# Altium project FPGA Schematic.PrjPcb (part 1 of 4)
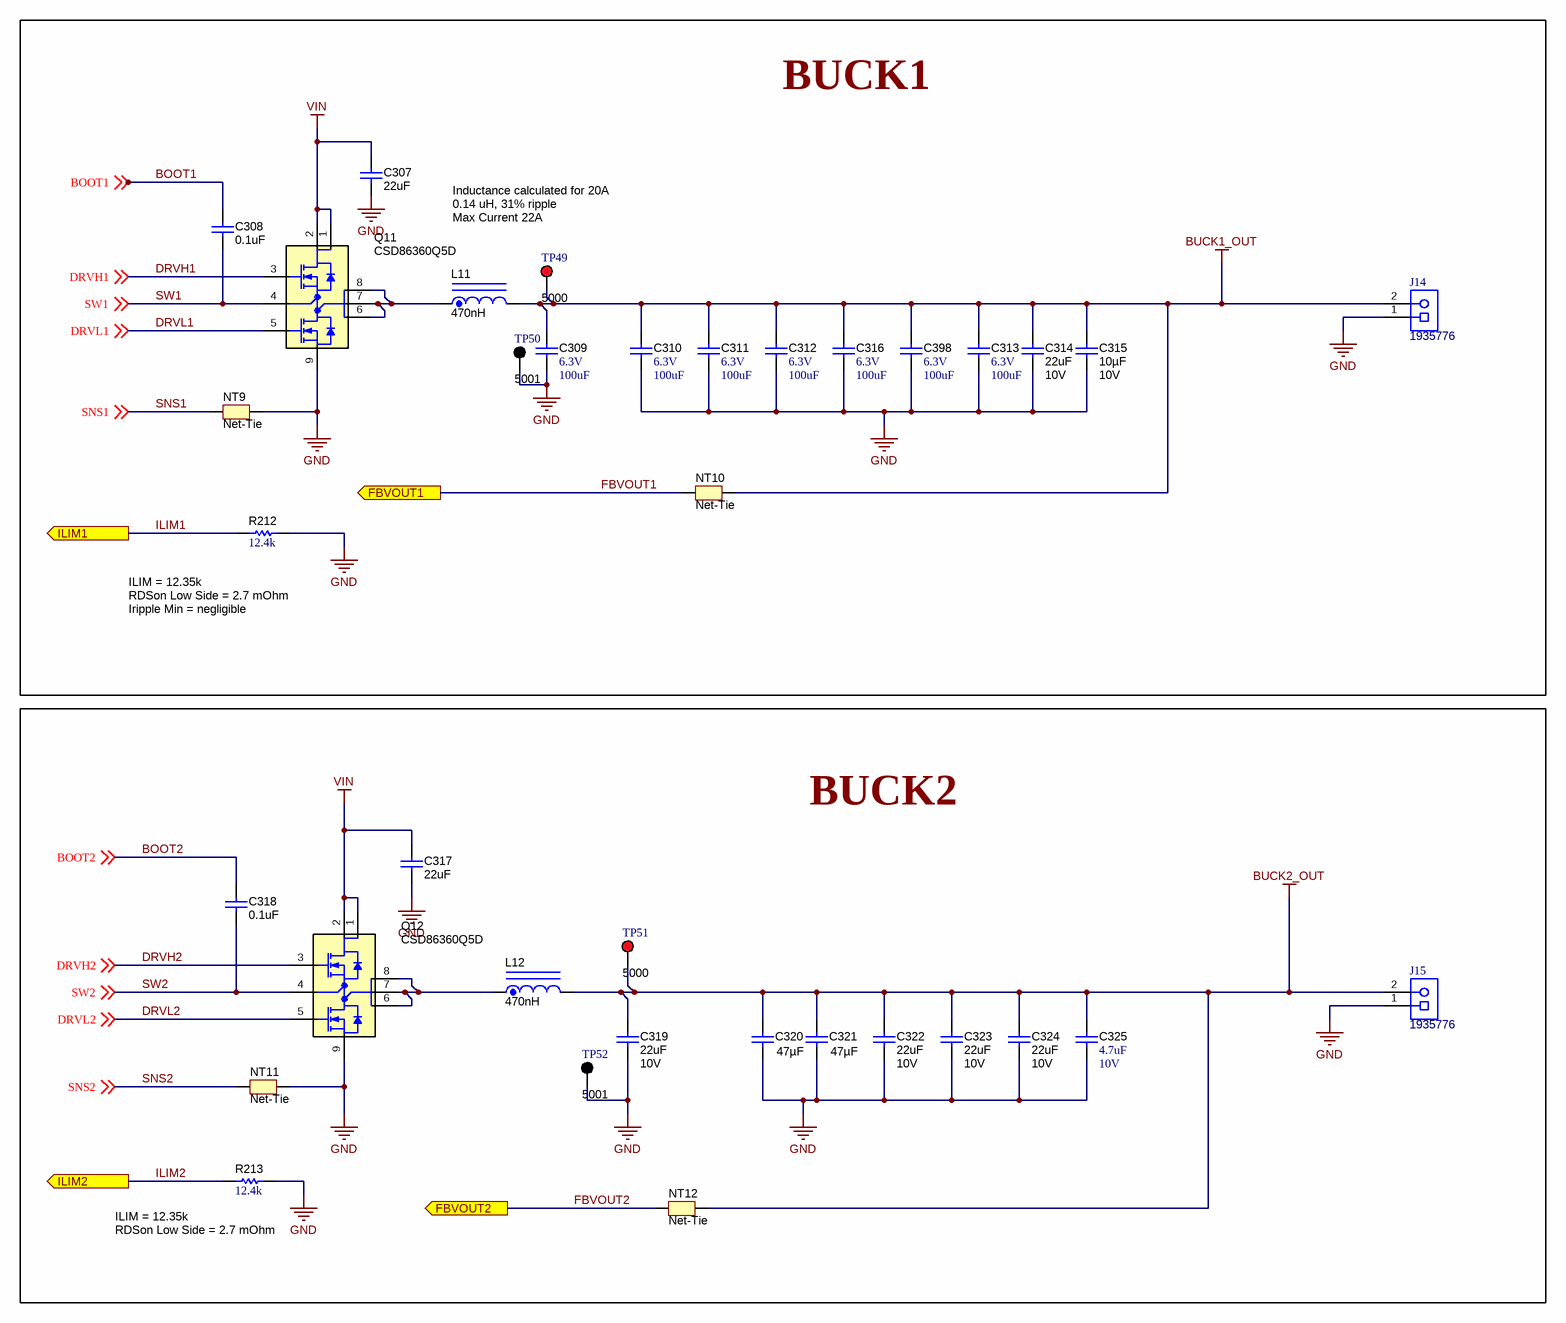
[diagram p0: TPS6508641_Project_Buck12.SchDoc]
TID: TIDA-010241; TechSupport: http://www.ti.com/support; SCH_Rev: E1; PRJ_Title: Flexible FPGA Power; PRJ_Number: TIDA-010241; PRJ_Engineer: Albert Lo; PRJ_Customer: Public Release; PCB_Rev: E1; PCB_Layout: Albert Lo; CopyrightYear: 2021
17 sheets, 877 parts. Net scope: flat (ports and power ports of the same name join across sheets).
Board file: PCB.PcbDoc
Sheets:
  TPS6508641_Project_Buck12.SchDoc
  TPS6508641_Project_Buck6.SchDoc
  TPS6508641_Project_Buck345.SchDoc
  TPS6508641_Project_TPS65086.SchDoc
  TPS6508641_Support_Devices.SchDoc
  TPSM5D1806 IND.SchDoc
  TPSM5D1806 Multi Phase.SchDoc
  EVRHC008_  Filters.SchDoc
  EVRHC008_ CONTROLLER_6X6.SchDoc
  EVRHC008_ Dynamic Load.SchDoc
  EVRHC008_Aux Power.SchDoc
  EVRHC008_HelperCkts and Indicators.SchDoc
  EVRHC008_VOUT_A_Phases 1-2-3.SchDoc
  EVRHC008_VOUT_A_Phases 4-5-6.SchDoc
  EVRHC008_VOUT_B_Phases 1-2.SchDoc
  Hardware.SchDoc
  Block Diagram.SchDoc

## Sheet TPS6508641_Project_Buck12.SchDoc
size 431 x 279 mm; Date: Not shown in title block; ApprovedBy: Not shown in title block; CheckedBy: Not shown in title block; Author: Not shown in title block; CompanyName: Not shown in title block; Engineer: Not shown in title block; Organization: Not shown in title block; Address1: Not shown in title block; Address2: Not shown in title block; Address3: Not shown in title block; Address4: Not shown in title block; DocumentNumber: 11; Revision: Use project parameter SCH_Rev; SheetNumber: 11; SheetTotal: 17; PageSetup: Record=PageOptions¦CenterHorizontal=True¦CenterVertical=True¦PrintScale=0.62¦XCorrection=1.00¦YCorrection=1.00¦PrintKind=0¦BorderSize=5000000¦LeftOffset=0¦BottomOffset=0¦Orientation=2¦PaperLength=1000¦PaperWidth=1000¦Scale=100¦PaperSource=15¦PrintQuality=600¦MediaType=1¦DitherType=10¦PrintScaleMode=1¦PaperKind=Letter

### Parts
C307  ValueDisplayed: 22uF  [0805L]  (hidden comment: GRM21BR61E226ME44L)
C308  ValueDisplayed: 0.1uF  [0201_033L]  (hidden comment: GRM033R61E104KE14J)
C309  VDC_V: 6.3V  ValueDisplayed: 100uF  [0805L]  (hidden comment: GRM21BR60J107M)
C310  VDC_V: 6.3V  ValueDisplayed: 100uF  [0805L]  (hidden comment: GRM21BR60J107M)
C311  VDC_V: 6.3V  ValueDisplayed: 100uF  [0805L]  (hidden comment: GRM21BR60J107M)
C312  VDC_V: 6.3V  ValueDisplayed: 100uF  [0805L]  (hidden comment: GRM21BR60J107M)
C313  VDC_V: 6.3V  ValueDisplayed: 100uF  [0805L]  (hidden comment: GRM21BR60J107M)
C314  ValueDisplayed: 22uF  VDC_V: 10V  [0603S]  (hidden comment: GRM188R61A226ME15D)
C315  ValueDisplayed: 10µF  VDC_V: 10V  [0603S]  (hidden comment: GRM188R61A106KAALD)
C316  VDC_V: 6.3V  ValueDisplayed: 100uF  [0805L]  (hidden comment: GRM21BR60J107M)
C317  ValueDisplayed: 22uF  [0805L]  (hidden comment: GRM21BR61E226ME44L)
C318  ValueDisplayed: 0.1uF  [0201_033L]  (hidden comment: GRM033R61E104KE14J)
C319  ValueDisplayed: 22uF  VDC_V: 10V  [0603S]  (hidden comment: GRM188R61A226ME15D)
C320  ValueDisplayed: 47µF  [0805L]  (hidden comment: GRM21BR61A476ME15L)
C321  ValueDisplayed: 47µF  [0805L]  (hidden comment: GRM21BR61A476ME15L)
C322  ValueDisplayed: 22uF  VDC_V: 10V  [0603S]  (hidden comment: GRM188R61A226ME15D)
C323  ValueDisplayed: 22uF  VDC_V: 10V  [0603S]  (hidden comment: GRM188R61A226ME15D)
C324  ValueDisplayed: 22uF  VDC_V: 10V  [0603S]  (hidden comment: GRM188R61A226ME15D)
C325  ValueDisplayed: 4.7uF  VDC_V: 10V  [0402S]  (hidden comment: GRM155R61A475M)
C398  VDC_V: 6.3V  ValueDisplayed: 100uF  [0805L]  (hidden comment: GRM21BR60J107M)
J14  1935776  [Phoenix_1935776]
J15  1935776  [Phoenix_1935776]
L11  ValueDisplayed: 470nH  [XEL6030_320]  (hidden comment: XEL6030-471MEB)
L12  ValueDisplayed: 470nH  [XEL6030_320]  (hidden comment: XEL6030-471MEB)
NT9  Net-Tie  [Net-Tie6milsWide_20milsLong]  (net tie, no BOM)
NT10  Net-Tie  [Net-Tie6milsWide_20milsLong]  (net tie, no BOM)
NT11  Net-Tie  [Net-Tie6milsWide_20milsLong]  (net tie, no BOM)
NT12  Net-Tie  [Net-Tie6milsWide_20milsLong]  (net tie, no BOM)
Q11  CSD86360Q5D  [DQY0008A]
Q12  CSD86360Q5D  [DQY0008A]
R212  ValueDisplayed: 12.4k  [0402S]  (hidden comment: CRCW040212K4FKED)
R213  ValueDisplayed: 12.4k  [0402S]  (hidden comment: CRCW040212K4FKED)
TP49  5000  [Keystone5000]
TP50  5001  [Keystone5001]
TP51  5000  [Keystone5000]
TP52  5001  [Keystone5001]

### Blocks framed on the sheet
BUCK1: C307-C316 C398 J14 L11 NT9 NT10 Q11 R212 TP49 TP50
BUCK2: C317-C325 J15 L12 NT11 NT12 Q12 R213 TP51 TP52

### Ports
FBVOUT1 (out), FBVOUT2 (out), ILIM1 (out), ILIM2 (out)

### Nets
BUCK1_OUT: C309.1 C310.1 C311.1 C312.1 C313.1 C314.2 C315.2 C316.1 C398.1 J14.2 L11.2 NT10.2 TP49.1
BUCK2_OUT: C319.2 C320.1 C321.1 C322.2 C323.2 C324.2 C325.1 J15.2 L12.2 NT12.2 TP51.1
GND: C307.2 C309.2 C310.2 C311.2 C312.2 C313.2 C314.1 C315.1 C316.2 C317.2 C319.1 C320.2 C321.2 C322.1 C323.1 C324.1 C325.2 C398.2 J14.1 J15.1 NT9.2 NT11.2 Q11.9(PGND) Q12.9(PGND) R212.2 R213.2 TP50.1 TP52.1
VIN: C307.1 C317.1 Q11.1(VIN) Q11.2(VIN) Q12.1(VIN) Q12.2(VIN)
BOOT1: C308.1 ; off-sheet BOOT1
BOOT2: C318.1 ; off-sheet BOOT2
DRVH1: Q11.3(TG) ; off-sheet DRVH1
DRVH2: Q12.3(TG) ; off-sheet DRVH2
DRVL1: Q11.5(BG) ; off-sheet DRVL1
DRVL2: Q12.5(BG) ; off-sheet DRVL2
FBVOUT1: NT10.1 ; port FBVOUT1
FBVOUT2: NT12.1 ; port FBVOUT2
ILIM1: R212.1 ; port ILIM1
ILIM2: R213.1 ; port ILIM2
SNS1: NT9.1 ; off-sheet SNS1
SNS2: NT11.1 ; off-sheet SNS2
SW1: C308.2 Q11.4(TGR) ; off-sheet SW1
SW2: C318.2 Q12.4(TGR) ; off-sheet SW2
NetL11_1: L11.1 Q11.6(VSW) Q11.7(VSW) Q11.8(VSW)
NetL12_1: L12.1 Q12.6(VSW) Q12.7(VSW) Q12.8(VSW)

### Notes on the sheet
- Inductance calculated for 20A
  0.14 uH, 31% ripple
  Max Current 22A
- (near R212) ILIM = 12.35k
  RDSon Low Side = 2.7 mOhm
  Iripple Min = negligible
- (near R213) ILIM = 12.35k
  RDSon Low Side = 2.7 mOhm

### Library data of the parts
C307 C317 = CMP-0008305-2: CAP, CERM, 22 uF, 25 V, +/- 20%, X5R, 0805; Manufacturer: MuRata; TaMin_C: -55°C; Polarized: N; SizeAreaWB_mm2: 6.75; Value1: Unknown; U/M: EA; Value: 22uF; TaMax_C: 85°C; SizeZ_mm: 1.45; SizeX_mm: 2; SizeY_mm: 1.25; Cap_Case: 0805; Value2: 25V; SizeArea_mm2: 2.5; Cap_F: 22µF; AEC Category: Q200
C308 C318 = CMP-0009719-2: CAP, CERM, 0.1 uF, 25 V, +/- 10%, X5R, 0201; Manufacturer: MuRata; TaMin_C: -55°C; Polarized: N; SizeAreaWB_mm2: 2.08; Value1: Unknown; U/M: EA; Value: 0.1uF; TaMax_C: 85°C; SizeZ_mm: 0.33; SizeX_mm: 0.6; SizeY_mm: 0.3; Cap_Case: 0201; Value2: 25V; SizeArea_mm2: 0.18; Cap_F: 100nF; AEC Category: Q200
C309-C313 C316 C398 = CMP-0008280-2: CAP, CERM, 100 uF, 6.3 V, +/- 20%, X5R, 0805; Manufacturer: MuRata; TaMin_C: -55°C; Polarized: N; SizeAreaWB_mm2: 6.75; Value1: Unknown; U/M: EA; Value: 100uF; TaMax_C: 85°C; SizeZ_mm: 1.45; SizeX_mm: 2; SizeY_mm: 1.25; Cap_Case: 0805; SizeArea_mm2: 2.5; Cap_F: 100µF; AEC Category: Q200
C314 C319 C322-C324 = CMP-0007324-5: CAP, CERM, 22 uF, 10 V, +/- 20%, X5R, 0603; Manufacturer: MuRata; Polarized: N; Value: 22uF; U/M: EA; Cap_F: 22µF; Value1: Unknown; TaMin_C: -55°C; TaMax_C: 85°C; Cap_Case: 0603; SizeArea_mm2: 1.28; SizeAreaWB_mm2: 4.68; SizeX_mm: 1.6; SizeY_mm: 0.8; SizeZ_mm: 1; AEC Category: Q200
C315 = CMP-0086193-1: CAP, CERM, 10 µF, 10 V,+/- 10%, X5R, 0603; Manufacturer: MuRata; Polarized: N; Value: 10uF; U/M: EA; TaMin_C: -55°C; TaMax_C: 85°C; Cap_Case: 0603; SizeArea_mm2: 1.28; SizeAreaWB_mm2: 4.68; SizeX_mm: 1.6; SizeY_mm: 0.8; SizeZ_mm: 1; AEC Category: Q200
C320 C321 = CMP-0078699-1: CAP, CERM, 47 µF, 10 V,+/- 20%, X5R, 0805; Manufacturer: MuRata; TaMin_C: -55°C; Polarized: N; Green_Lifecycle: Active; SizeAreaWB_mm2: 6.75; Green_REACh: Passed; U/M: EA; Value: 47uF; TaMax_C: 85°C; SizeZ_mm: 1.45; SizeX_mm: 2; SizeY_mm: 1.25; Cap_Case: 0805; Value2: 10V; SizeArea_mm2: 2.5; AEC Category: Q200
C325 = CMP-0006581-2: CAP, CERM, 4.7 uF, 10 V, +/- 20%, X5R, 0402; Manufacturer: MuRata; Polarized: N; Value: 4.7uF; U/M: EA; Cap_F: 4.7µF; Value1: Unknown; TaMin_C: -55°C; TaMax_C: 85°C; Cap_Case: 0402; SizeArea_mm2: 0.5; SizeAreaWB_mm2: 3; SizeX_mm: 1; SizeZ_mm: 0.6; AEC Category: Q200
J14 J15 = CMP-0055506-1: Terminal Block, 2x1, 5mm, Green, TH; Manufacturer: Phoenix Contact; Pitch_mm: 5; Gender: Female; Row_Count: 1; CNHeader: FALSE; Green_Lifecycle: Not Set; Green_REACh: Incomplete; CT: TRUE
L11 = CMP-0061103-3: Inductor, Shielded, Composite, 470 nH, 22.3 A, 0.00331 ohm, AEC-Q200 Grade 1, SMD; Manufacturer: Coilcraft; Irms: 22.3A @ 40C rise; Value2: 22.3A; AEC Category: Q200; DCR_ohm: 3.31m; SizeX_mm: 6.36; SizeArea_mm2: 41.7216; SizeAreaWB_mm2: 71.5616; AEC Grade: 1; SizeY_mm: 6.56; Isat: 24A @ 30% inductance drop; SizeZ_mm: 3.2; Value: 470nH; AEC Qualified: Y
L12 = CMP-0061103-3: Inductor, Shielded, Composite, 470 nH, 22.3 A, 0.00331 ohm, AEC-Q200 Grade 1, SMD; Manufacturer: Coilcraft; Isat: 24A @ 30% inductance drop; Irms: 22.3A @ 40C rise; SizeAreaWB_mm2: 71.5616; DCR_ohm: 3.31m; Value: 470nH; Imax_A: 22.3A; SizeZ_mm: 3.2; SizeX_mm: 6.36; SizeY_mm: 6.56; SizeArea_mm2: 41.7216; AEC Qualified: Y; AEC Grade: 1; AEC Category: Q200
NT9-NT12 = CMP-0078142-4: Single point connection between nets.
Q11 Q12 = CMP-0000278-2: MOSFET, 2-CH, N-CH, 25 V, 50 A, DQY0008A (LSON-CLIP-8); Alternate Manufacturer: None; Manufacturer: Texas Instruments; SizeZ_mm: 1.6; ChType: N; Value2: 9.7 nC; Value1: 0.004; VdsMax_V: 25V; SizeX_mm: 6; SizeY_mm: 5; Vgs_V: 10V; Value: 25V; Rdson45_ohm: 4.5m; SizeArea_mm2: 30; AEC Category: Q101; IdsMax_A: 50A; SizeAreaWB_mm2: 56; QgTyp_nC: 9.7; ChMode: Enhancement
R212 R213 = CMP-0025992-3: RES, 12.4 k, 1%, 0.063 W, AEC-Q200 Grade 0, 0402; Manufacturer: Vishay-Dale; Power_W: 63mW; TempCo: 100 ppm/C; Value_Code: 12k4; Value: 12.4k; EIA_Code: E96; SizeX_mm: 1; SizeY_mm: 0.5; SizeZ_mm: 0.6; Value2: 0.063W; AEC Qualified: Y; VDC_V: 50V; AEC Category: Q200; AEC Grade: 0
TP49 TP51 = CMP-0055137-1: Test Point, Miniature, Red, TH; Manufacturer: Keystone; ContactFinish: Silver; CNHeader: FALSE; Green_Lifecycle: Active; Green_REACh: Passed; CT: TRUE
TP50 TP52 = CMP-0055138-1: Test Point, Miniature, Black, TH; Manufacturer: Keystone; ContactFinish: Silver; CNHeader: FALSE; Green_Lifecycle: Active; Green_REACh: Passed; CT: TRUE

## Sheet TPS6508641_Project_Buck6.SchDoc
size 431 x 279 mm; Date: Not shown in title block; ApprovedBy: Not shown in title block; CheckedBy: Not shown in title block; Author: Not shown in title block; CompanyName: Not shown in title block; Engineer: Not shown in title block; Organization: Not shown in title block; Address1: Not shown in title block; Address2: Not shown in title block; Address3: Not shown in title block; Address4: Not shown in title block; DocumentNumber: 12; Revision: Use project parameter SCH_Rev; SheetNumber: 12; SheetTotal: 17; PageSetup: Record=PageOptions¦CenterHorizontal=True¦CenterVertical=True¦PrintScale=1.00¦XCorrection=1.00¦YCorrection=1.00¦PrintKind=0¦BorderSize=5000000¦LeftOffset=0¦BottomOffset=0¦Orientation=2¦PaperLength=1000¦PaperWidth=1000¦Scale=100¦PaperSource=15¦PrintQuality=600¦MediaType=1¦DitherType=10¦PaperKind=Letter¦PrintScaleMode=1
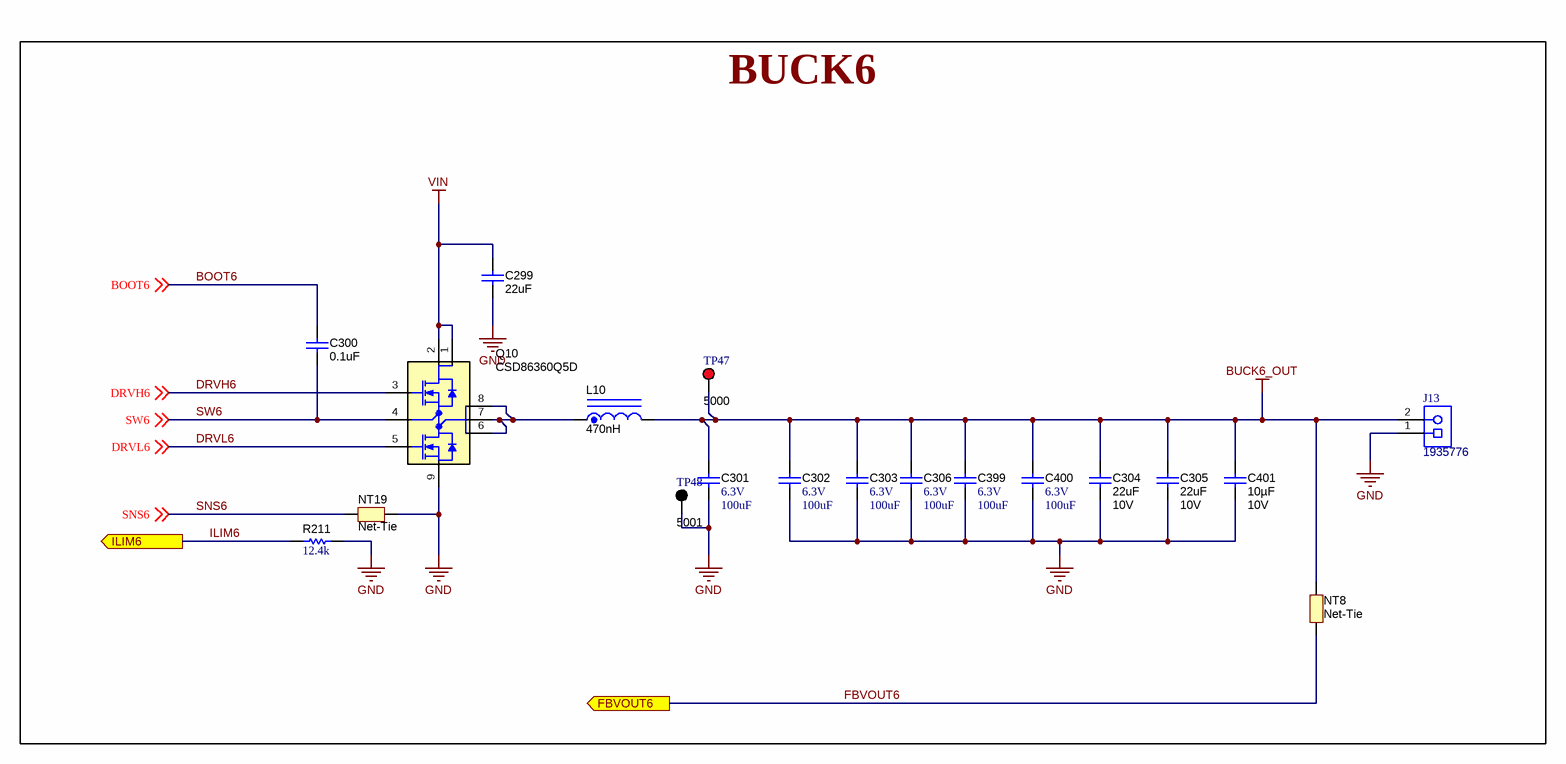
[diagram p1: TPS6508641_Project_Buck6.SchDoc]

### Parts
C299  ValueDisplayed: 22uF  [0805L]  (hidden comment: GRM21BR61E226ME44L)
C300  ValueDisplayed: 0.1uF  [0201_033L]  (hidden comment: GRM033R61E104KE14J)
C301  VDC_V: 6.3V  ValueDisplayed: 100uF  [0805L]  (hidden comment: GRM21BR60J107M)
C302  VDC_V: 6.3V  ValueDisplayed: 100uF  [0805L]  (hidden comment: GRM21BR60J107M)
C303  VDC_V: 6.3V  ValueDisplayed: 100uF  [0805L]  (hidden comment: GRM21BR60J107M)
C304  ValueDisplayed: 22uF  VDC_V: 10V  [0603S]  (hidden comment: GRM188R61A226ME15D)
C305  ValueDisplayed: 22uF  VDC_V: 10V  [0603S]  (hidden comment: GRM188R61A226ME15D)
C306  VDC_V: 6.3V  ValueDisplayed: 100uF  [0805L]  (hidden comment: GRM21BR60J107M)
C399  VDC_V: 6.3V  ValueDisplayed: 100uF  [0805L]  (hidden comment: GRM21BR60J107M)
C400  VDC_V: 6.3V  ValueDisplayed: 100uF  [0805L]  (hidden comment: GRM21BR60J107M)
C401  ValueDisplayed: 10µF  VDC_V: 10V  [0603S]  (hidden comment: GRM188R61A106KAALD)
J13  1935776  [Phoenix_1935776]
L10  ValueDisplayed: 470nH  [XEL6030_320]  (hidden comment: XEL6030-471MEB)
NT8  Net-Tie  [Net-Tie6milsWide_20milsLong]  (net tie, no BOM)
NT19  Net-Tie  [Net-Tie6milsWide_20milsLong]  (net tie, no BOM)
Q10  CSD86360Q5D  [DQY0008A]
R211  ValueDisplayed: 12.4k  [0402S]  (hidden comment: CRCW040212K4FKED)
TP47  5000  [Keystone5000]
TP48  5001  [Keystone5001]

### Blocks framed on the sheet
BUCK6: C299-C306 C399-C401 J13 L10 NT8 NT19 Q10 R211 TP47 TP48

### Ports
FBVOUT6 (out), ILIM6 (out)

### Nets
BUCK6_OUT: C301.1 C302.1 C303.1 C304.2 C305.2 C306.1 C399.1 C400.1 C401.2 J13.2 L10.2 NT8.2 TP47.1
GND: C299.2 C301.2 C302.2 C303.2 C304.1 C305.1 C306.2 C399.2 C400.2 C401.1 J13.1 NT19.2 Q10.9(PGND) R211.2 TP48.1
VIN: C299.1 Q10.1(VIN) Q10.2(VIN)
BOOT6: C300.1 ; off-sheet BOOT6
DRVH6: Q10.3(TG) ; off-sheet DRVH6
DRVL6: Q10.5(BG) ; off-sheet DRVL6
FBVOUT6: NT8.1 ; port FBVOUT6
ILIM6: R211.1 ; port ILIM6
SNS6: NT19.1 ; off-sheet SNS6
SW6: C300.2 Q10.4(TGR) ; off-sheet SW6
NetL10_1: L10.1 Q10.6(VSW) Q10.7(VSW) Q10.8(VSW)

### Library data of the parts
C299 = CMP-0008305-2: as C307 on sheet TPS6508641_Project_Buck12
C300 = CMP-0009719-2: as C308 on sheet TPS6508641_Project_Buck12
C301-C303 C306 C399 C400 = CMP-0008280-2: as C309 on sheet TPS6508641_Project_Buck12
C304 C305 = CMP-0007324-5: as C314 on sheet TPS6508641_Project_Buck12
C401 = CMP-0086193-1: as C315 on sheet TPS6508641_Project_Buck12
J13 = CMP-0055506-1: as J14 on sheet TPS6508641_Project_Buck12
L10 = CMP-0061103-3: as L12 on sheet TPS6508641_Project_Buck12
NT8 NT19 = CMP-0078142-4: Single point connection between nets.
Q10 = CMP-0000278-2: as Q11 on sheet TPS6508641_Project_Buck12
R211 = CMP-0025992-3: as R212 on sheet TPS6508641_Project_Buck12
TP47 = CMP-0055137-1: as TP49 on sheet TPS6508641_Project_Buck12
TP48 = CMP-0055138-1: as TP50 on sheet TPS6508641_Project_Buck12

## Sheet TPS6508641_Project_Buck345.SchDoc
size 431 x 279 mm; Date: Not shown in title block; ApprovedBy: Not shown in title block; CheckedBy: Not shown in title block; Author: Not shown in title block; CompanyName: Not shown in title block; Engineer: Not shown in title block; Organization: Not shown in title block; Address1: Not shown in title block; Address2: Not shown in title block; Address3: Not shown in title block; Address4: Not shown in title block; DocumentNumber: 13; Revision: Use project parameter SCH_Rev; SheetNumber: 13; SheetTotal: 17; PageSetup: Record=PageOptions¦CenterHorizontal=True¦CenterVertical=True¦PrintScale=1.00¦XCorrection=1.00¦YCorrection=1.00¦PrintKind=0¦BorderSize=5000000¦LeftOffset=0¦BottomOffset=0¦Orientation=2¦PaperLength=1000¦PaperWidth=1000¦Scale=100¦PaperSource=15¦PrintQuality=600¦MediaType=1¦DitherType=10¦PaperKind=Letter¦PrintScaleMode=1
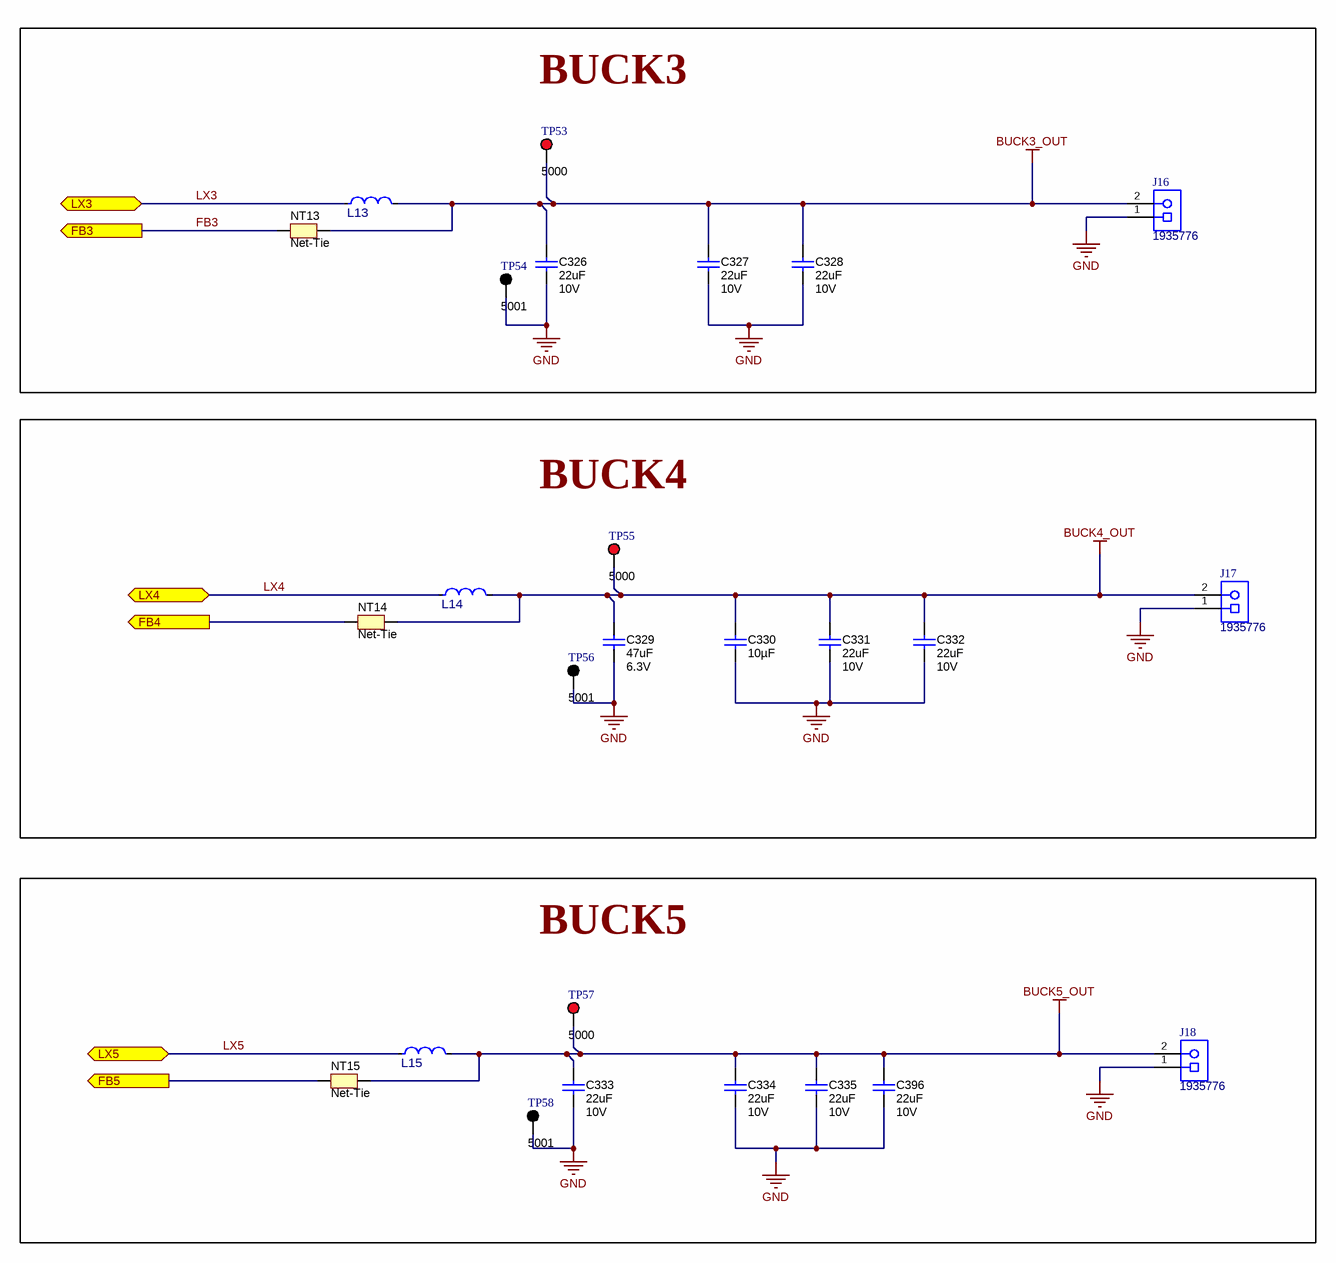
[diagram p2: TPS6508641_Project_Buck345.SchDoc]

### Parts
C326  ValueDisplayed: 22uF  VDC_V: 10V  [0603S]  (hidden comment: GRM188R61A226ME15D)
C327  ValueDisplayed: 22uF  VDC_V: 10V  [0603S]  (hidden comment: GRM188R61A226ME15D)
C328  ValueDisplayed: 22uF  VDC_V: 10V  [0603S]  (hidden comment: GRM188R61A226ME15D)
C329  ValueDisplayed: 47uF  VDC_V: 6.3V  [0603S]  (hidden comment: GRM188R60J476ME15D)
C330  ValueDisplayed: 10µF  [0603S]  (hidden comment: GRM188R61A106KAALD)
C331  ValueDisplayed: 22uF  VDC_V: 10V  [0603S]  (hidden comment: GRM188R61A226ME15D)
C332  ValueDisplayed: 22uF  VDC_V: 10V  [0603S]  (hidden comment: GRM188R61A226ME15D)
C333  ValueDisplayed: 22uF  VDC_V: 10V  [0603S]  (hidden comment: GRM188R61A226ME15D)
C334  ValueDisplayed: 22uF  VDC_V: 10V  [0603S]  (hidden comment: GRM188R61A226ME15D)
C335  ValueDisplayed: 22uF  VDC_V: 10V  [0603S]  (hidden comment: GRM188R61A226ME15D)
C396  ValueDisplayed: 22uF  VDC_V: 10V  [0603S]  (hidden comment: GRM188R61A226ME15D)
J16  1935776  [Phoenix_1935776]
J17  1935776  [Phoenix_1935776]
J18  1935776  [Phoenix_1935776]
L13  XEL3530-501MEC  [FP-XEL3530-501MEC_SMT_IND_3MM2_3MM5-MFG]  (value not drawn)
L14  XEL3530-501MEC  [FP-XEL3530-501MEC_SMT_IND_3MM2_3MM5-MFG]  (value not drawn)
L15  XEL3530-501MEC  [FP-XEL3530-501MEC_SMT_IND_3MM2_3MM5-MFG]  (value not drawn)
NT13  Net-Tie  [Net-Tie6milsWide_20milsLong]  (net tie, no BOM)
NT14  Net-Tie  [Net-Tie6milsWide_20milsLong]  (net tie, no BOM)
NT15  Net-Tie  [Net-Tie6milsWide_20milsLong]  (net tie, no BOM)
TP53  5000  [Keystone5000]
TP54  5001  [Keystone5001]
TP55  5000  [Keystone5000]
TP56  5001  [Keystone5001]
TP57  5000  [Keystone5000]
TP58  5001  [Keystone5001]

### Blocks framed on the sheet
BUCK3: C326-C328 J16 L13 NT13 TP53 TP54
BUCK4: C329-C332 J17 L14 NT14 TP55 TP56
BUCK5: C333-C335 C396 J18 L15 NT15 TP57 TP58

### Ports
FB3 (out), FB4 (out), FB5 (out), LX3 (bidir), LX4 (bidir), LX5 (bidir)

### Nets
BUCK3_OUT: C326.2 C327.2 C328.2 J16.2 L13.2 NT13.2 TP53.1
BUCK4_OUT: C329.1 C330.1 C331.2 C332.2 J17.2 L14.2 NT14.2 TP55.1
BUCK5_OUT: C333.2 C334.2 C335.2 C396.2 J18.2 L15.2 NT15.2 TP57.1
GND: C326.1 C327.1 C328.1 C329.2 C330.2 C331.1 C332.1 C333.1 C334.1 C335.1 C396.1 J16.1 J17.1 J18.1 TP54.1 TP56.1 TP58.1
FB3: NT13.1 ; port FB3
FB4: NT14.1 ; port FB4
FB5: NT15.1 ; port FB5
LX3: L13.1 ; port LX3
LX4: L14.1 ; port LX4
LX5: L15.1 ; port LX5

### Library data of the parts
C326-C328 C331-C335 C396 = CMP-0007324-5: as C314 on sheet TPS6508641_Project_Buck12
C329 = CMP-0007313-5: CAP, CERM, 47 uF, 6.3 V, +/- 20%, X5R, 0603; Manufacturer: MuRata; Polarized: N; Value: 47uF; U/M: EA; Cap_F: 47µF; Value1: Unknown; TaMin_C: -55°C; TaMax_C: 85°C; Cap_Case: 0603; SizeArea_mm2: 1.28; SizeAreaWB_mm2: 4.68; SizeX_mm: 1.6; SizeY_mm: 0.8; SizeZ_mm: 1; AEC Category: Q200
C330 = CMP-0086193-1: CAP, CERM, 10 µF, 10 V,+/- 10%, X5R, 0603; Manufacturer: MuRata; SizeArea_mm2: 1.28; SizeY_mm: 0.8; TaMax_C: 85°C; TaMin_C: -55°C; VDC_V: 10V; Polarized: N; SizeAreaWB_mm2: 4.68; SizeZ_mm: 1; SizeX_mm: 1.6; AEC Category: Q200; Cap_Case: 0603; U/M: EA; Value: 10uF
J16-J18 = CMP-0055506-1: as J14 on sheet TPS6508641_Project_Buck12
L13-L15 = CMP-0087112-1: Shielded Power Inductors; Manufacturer: Coilcraft; Isat: 3.7A; Irms: 8.5A; DCR_ohm: 8.35m; Material: Composite; SizeZ_mm: 3mm; Ind_H: 500nH; AEC Qualified: Yes; AEC Grade: Grade 1
NT13-NT15 = CMP-0078142-4: Single point connection between nets.
TP53 TP55 TP57 = CMP-0055137-1: as TP49 on sheet TPS6508641_Project_Buck12
TP54 TP56 TP58 = CMP-0055138-1: as TP50 on sheet TPS6508641_Project_Buck12

## Sheet TPS6508641_Project_TPS65086.SchDoc
size 431 x 279 mm; Date: Not shown in title block; ApprovedBy: Not shown in title block; CheckedBy: Not shown in title block; Author: Not shown in title block; CompanyName: Not shown in title block; Engineer: Not shown in title block; Organization: Not shown in title block; Address1: Not shown in title block; Address2: Not shown in title block; Address3: Not shown in title block; Address4: Not shown in title block; DocumentNumber: 10; Revision: Use project parameter SCH_Rev; SheetNumber: 10; SheetTotal: 17; PageSetup: Record=PageOptions¦CenterHorizontal=True¦CenterVertical=True¦PrintScale=1.00¦XCorrection=1.00¦YCorrection=1.00¦PrintKind=0¦BorderSize=5000000¦LeftOffset=0¦BottomOffset=0¦Orientation=2¦PaperLength=1000¦PaperWidth=1000¦Scale=100¦PaperSource=15¦PrintQuality=600¦MediaType=1¦DitherType=10¦PaperKind=Letter¦PrintScaleMode=1
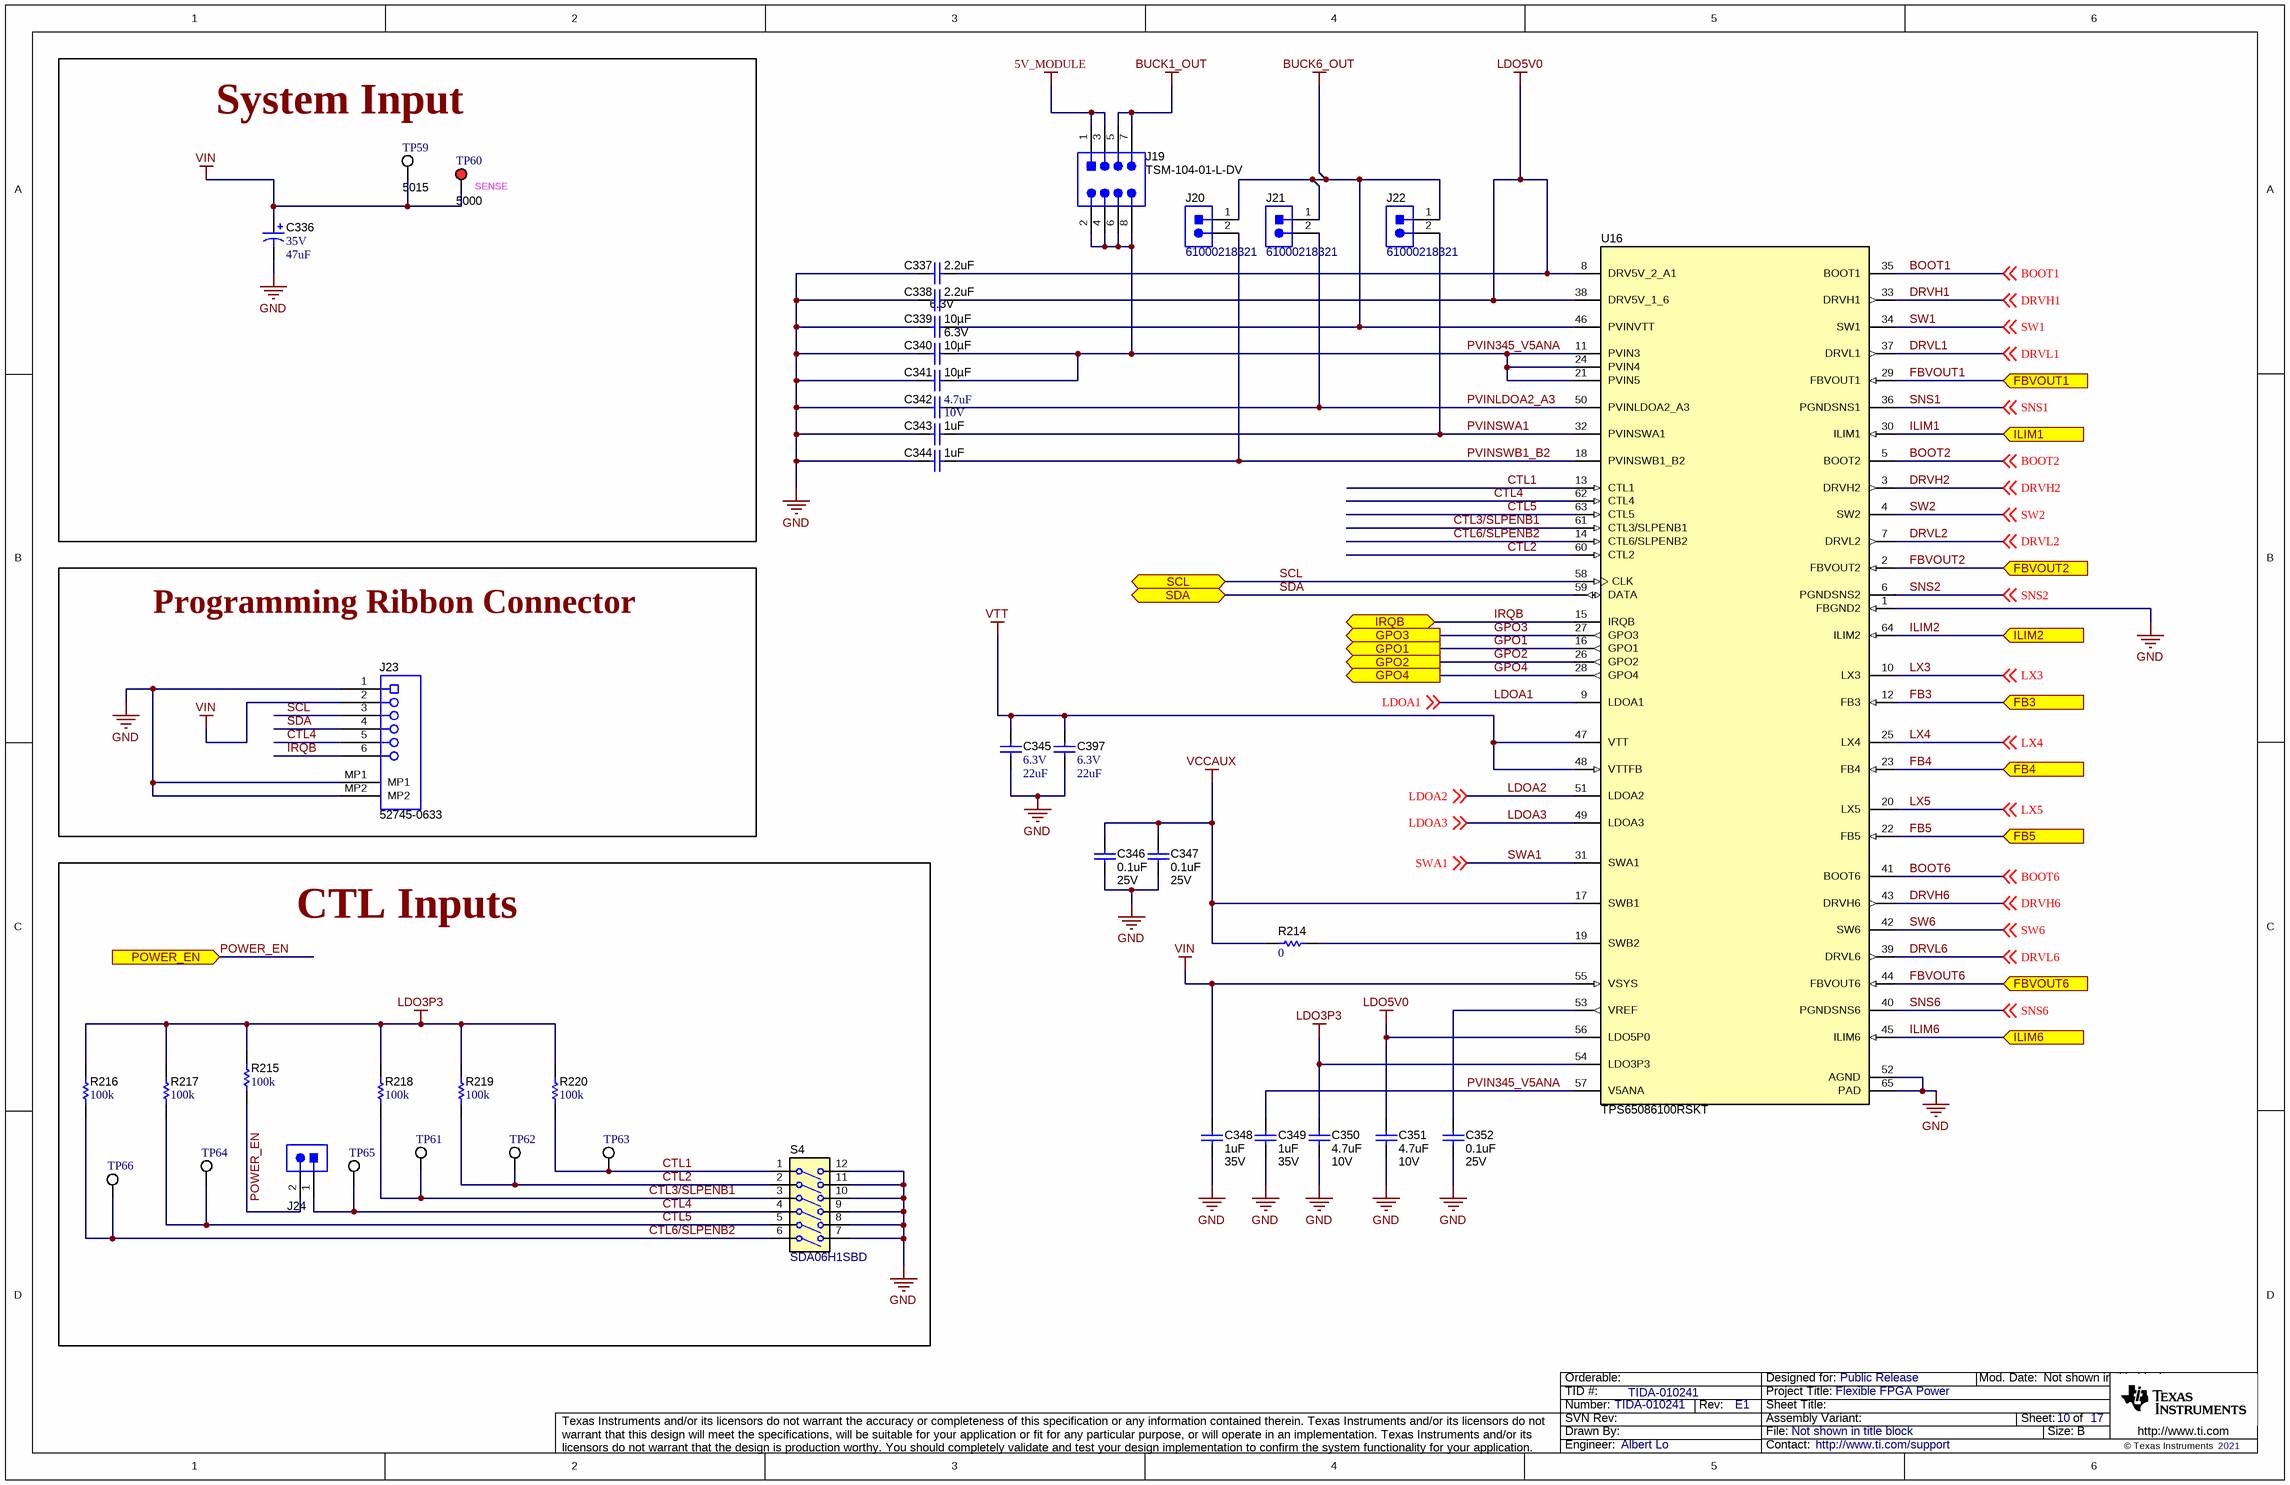
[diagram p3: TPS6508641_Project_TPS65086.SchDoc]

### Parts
C336  VDC_V: 35V  ValueDisplayed: 47uF  [7343-43]  (hidden comment: TAJE476M035RNJ)
C337  ValueDisplayed: 2.2uF  VDC_V: 6.3V  [0402S]  (hidden comment: GRM155R60J225KE95D)
C338  ValueDisplayed: 2.2uF  VDC_V: 6.3V  [0402S]  (hidden comment: GRM155R60J225KE95D)
C339  ValueDisplayed: 10µF  [0603S]  (hidden comment: GRM188R61A106KAALD)
C340  ValueDisplayed: 10µF  [0603S]  (hidden comment: GRM188R61A106KAALD)
C341  ValueDisplayed: 10µF  [0603S]  (hidden comment: GRM188R61A106KAALD)
C342  VDC_V: 10V  ValueDisplayed: 4.7uF  [0402_065]  (hidden comment: C1005X5R1A475K050BC)
C343  ValueDisplayed: 1uF  [0201L]  (hidden comment: GRM033R61A105ME15D)
C344  ValueDisplayed: 1uF  [0201L]  (hidden comment: GRM033R61A105ME15D)
C345  VDC_V: 6.3V  ValueDisplayed: 22uF  [0402S]  (hidden comment: GRM155R60J226ME11D)
C346  ValueDisplayed: 0.1uF  VDC_V: 25V  [0201_033L]  (hidden comment: GRM033R61E104KE14J)
C347  ValueDisplayed: 0.1uF  VDC_V: 25V  [0201_033L]  (hidden comment: GRM033R61E104KE14J)
C348  ValueDisplayed: 1uF  VDC_V: 35V  [0402S]  (hidden comment: GRM155R6YA105ME11D)
C349  ValueDisplayed: 1uF  VDC_V: 35V  [0402S]  (hidden comment: GRM155R6YA105ME11D)
C350  ValueDisplayed: 4.7uF  VDC_V: 10V  [0402S]  (hidden comment: C1005X5R1A475M050BC)
C351  ValueDisplayed: 4.7uF  VDC_V: 10V  [0402S]  (hidden comment: C1005X5R1A475M050BC)
C352  ValueDisplayed: 0.1uF  VDC_V: 25V  [0201_033L]  (hidden comment: GRM033R61E104KE14J)
C397  VDC_V: 6.3V  ValueDisplayed: 22uF  [0402S]  (hidden comment: GRM155R60J226ME11D)
J19  TSM-104-01-L-DV  [Samtec_TSM-104-01-x-DV]
J20  61000218321  [Wurth_61000218321]
J21  61000218321  [Wurth_61000218321]
J22  61000218321  [Wurth_61000218321]
J23  52745-0633  [Molex_52745-0633]
J24  TSW-102-07-G-S  [TSW-102-07-G-S]  (value not drawn)
R214  ValueDisplayed: 0  [0402S]  (hidden comment: CRCW04020000Z0ED)
R215  ValueDisplayed: 100k  [0402S]  (hidden comment: CRCW0402100KJNED)
R216  ValueDisplayed: 100k  [0402S]  (hidden comment: CRCW0402100KJNED)
R217  ValueDisplayed: 100k  [0402S]  (hidden comment: CRCW0402100KJNED)
R218  ValueDisplayed: 100k  [0402S]  (hidden comment: CRCW0402100KJNED)
R219  ValueDisplayed: 100k  [0402S]  (hidden comment: CRCW0402100KJNED)
R220  ValueDisplayed: 100k  [0402S]  (hidden comment: CRCW0402100KJNED)
S4  SDA06H1SBD  [SW_SDA06H1SBD]
TP59  5015  [Testpoint_Keystone_Miniature]
TP60  5000  [Keystone5000]
TP61  5015  [Testpoint_Keystone_Miniature]  (value not drawn)
TP62  5015  [Testpoint_Keystone_Miniature]  (value not drawn)
TP63  5015  [Testpoint_Keystone_Miniature]  (value not drawn)
TP64  5015  [Testpoint_Keystone_Miniature]  (value not drawn)
TP65  5015  [Testpoint_Keystone_Miniature]  (value not drawn)
TP66  5015  [Testpoint_Keystone_Miniature]  (value not drawn)
U16  TPS65086100RSKT  [RSK0064C]

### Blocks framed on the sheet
System Input: C336 TP59 TP60
Programming Ribbon Connector: J23
CTL Inputs: J24 R215-R220 S4 TP61-TP66

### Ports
FB3 (in), FB4 (in), FB5 (in), FBVOUT1 (in), FBVOUT2 (in), FBVOUT6 (in), GPO1 (out), GPO2 (out), GPO3 (out), GPO4 (out), ILIM1 (in), ILIM2 (in), ILIM6 (in), IRQB (bidir), POWER_EN (in), SCL (bidir), SDA (bidir)

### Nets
5V_MODULE: J19.1 J19.3
BUCK1_OUT: J19.5 J19.7
BUCK6_OUT: C339.1 J20.1 J21.1 J22.1 U16.46(PVINVTT)
GND: C336.2(-) C337.2 C338.2 C339.2 C340.2 C341.2 C342.2 C343.2 C344.2 C345.2 C346.2 C347.2 C348.2 C349.2 C350.2 C351.2 C352.2 C397.2 J23.1 J23.MP1 J23.MP2 S4.7(6A) S4.8(5A) S4.9(4A) S4.10(3A) S4.11(2A) S4.12(1A) U16.1(FBGND2) U16.52(AGND) U16.65(PAD)
LDO3P3: C350.1 R215.2 R216.2 R217.2 R218.2 R219.2 R220.2 U16.54(LDO3P3)
LDO5V0: C337.1 C338.1 C351.1 U16.8(DRV5V_2_A1) U16.38(DRV5V_1_6) U16.56(LDO5P0)
VCCAUX: C346.1 C347.1 R214.2 U16.17(SWB1)
VIN: C336.1(+) C348.1 J23.2 TP59.1 TP60.1 U16.55(VSYS)
VTT: C345.1 C397.1 U16.47(VTT) U16.48(VTTFB)
BOOT1: U16.35(BOOT1) ; off-sheet BOOT1
BOOT2: U16.5(BOOT2) ; off-sheet BOOT2
BOOT6: U16.41(BOOT6) ; off-sheet BOOT6
CTL1: R220.1 S4.1 TP63.1 U16.13(CTL1)
CTL2: R219.1 S4.2 TP62.1 U16.60(CTL2)
CTL3/SLPENB1: R218.1 S4.3 TP61.1 U16.61(CTL3/SLPENB1)
CTL4: J23.5 J24.1 S4.4 TP65.1 U16.62(CTL4)
CTL5: R217.1 S4.5 TP64.1 U16.63(CTL5)
CTL6/SLPENB2: R216.1 S4.6 TP66.1 U16.14(CTL6/SLPENB2)
DRVH1: U16.33(DRVH1) ; off-sheet DRVH1
DRVH2: U16.3(DRVH2) ; off-sheet DRVH2
DRVH6: U16.43(DRVH6) ; off-sheet DRVH6
DRVL1: U16.37(DRVL1) ; off-sheet DRVL1
DRVL2: U16.7(DRVL2) ; off-sheet DRVL2
DRVL6: U16.39(DRVL6) ; off-sheet DRVL6
FB3: U16.12(FB3) ; port FB3
FB4: U16.23(FB4) ; port FB4
FB5: U16.22(FB5) ; port FB5
FBVOUT1: U16.29(FBVOUT1) ; port FBVOUT1
FBVOUT2: U16.2(FBVOUT2) ; port FBVOUT2
FBVOUT6: U16.44(FBVOUT6) ; port FBVOUT6
GPO1: U16.16(GPO1) ; port GPO1
GPO2: U16.26(GPO2) ; port GPO2
GPO3: U16.27(GPO3) ; port GPO3
GPO4: U16.28(GPO4) ; port GPO4
ILIM1: U16.30(ILIM1) ; port ILIM1
ILIM2: U16.64(ILIM2) ; port ILIM2
ILIM6: U16.45(ILIM6) ; port ILIM6
IRQB: J23.6 U16.15(IRQB) ; port IRQB
LDOA1: U16.9(LDOA1) ; off-sheet LDOA1
LDOA2: U16.51(LDOA2) ; off-sheet LDOA2
LDOA3: U16.49(LDOA3) ; off-sheet LDOA3
LX3: U16.10(LX3) ; off-sheet LX3
LX4: U16.25(LX4) ; off-sheet LX4
LX5: U16.20(LX5) ; off-sheet LX5
POWER_EN: J24.2 R215.1 ; port POWER_EN
PVIN345_V5ANA: C340.1 C341.1 C349.1 J19.2 J19.4 J19.6 J19.8 U16.11(PVIN3) U16.21(PVIN5) U16.24(PVIN4) U16.57(V5ANA)
PVINLDOA2_A3: C342.1 J21.2 U16.50(PVINLDOA2_A3)
PVINSWA1: C343.1 J22.2 U16.32(PVINSWA1)
PVINSWB1_B2: C344.1 J20.2 U16.18(PVINSWB1_B2)
SCL: J23.3 U16.58(CLK) ; port SCL
SDA: J23.4 U16.59(DATA) ; port SDA
SNS1: U16.36(PGNDSNS1) ; off-sheet SNS1
SNS2: U16.6(PGNDSNS2) ; off-sheet SNS2
SNS6: U16.40(PGNDSNS6) ; off-sheet SNS6
SW1: U16.34(SW1) ; off-sheet SW1
SW2: U16.4(SW2) ; off-sheet SW2
SW6: U16.42(SW6) ; off-sheet SW6
SWA1: U16.31(SWA1) ; off-sheet SWA1
NetC352_1: C352.1 U16.53(VREF)
NetR214_1: R214.1 U16.19(SWB2)

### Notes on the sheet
- (near TP60) SENSE

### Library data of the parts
C336 = CMP-0011853-2: CAP, TA, 47 uF, 35 V, +/- 20%, 0.9 ohm, AEC-Q200 Grade 1, SMD; Manufacturer: AVX; TaMin_C: -55°C; ESR_ohm: 0.9; Polarized: Y; SizeAreaWB_mm2: 58.59; Value1: 0.9 ohm; U/M: EA; Value: 47uF; TaMax_C: 125°C; SizeZ_mm: 4.3; SizeX_mm: 7.3; SizeArea_mm2: 31.39; CompType: Capacitor; Cap_F: 47µF; IRMS_A: 428mA; AEC Grade: 1; AEC Category: Q200
C337 C338 = CMP-0006543-2: CAP, CERM, 2.2 uF, 6.3 V, +/- 10%, X5R, 0402; Manufacturer: MuRata; Polarized: N; Value: 2.2uF; U/M: EA; Cap_F: 2.2µF; Value1: Unknown; TaMin_C: -55°C; TaMax_C: 85°C; Cap_Case: 0402; SizeArea_mm2: 0.5; SizeAreaWB_mm2: 3; SizeX_mm: 1; SizeZ_mm: 0.6; AEC Category: Q200
C339-C341 = CMP-0086193-1: as C330 on sheet TPS6508641_Project_Buck345
C342 = CMP-0006268-1: CAP, CERM, 4.7 uF, 10 V, +/- 10%, X5R, 0402; Manufacturer: TDK; TaMin_C: -55°C; ESR_ohm: 3.417m; Polarized: N; SizeAreaWB_mm2: 3; Value1: 0.003417 ohm; U/M: EA; Value: 4.7uF; TaMax_C: 85°C; SizeZ_mm: 0.65; SizeX_mm: 1; SizeY_mm: 0.5; Cap_F: 4.7µF; IRMS_A: 2.7063A; AEC Category: Q200
C343 C344 = CMP-0064909-1: CAP, CERM, 1 uF, 10 V,+/- 20%, X5R, 0201; Manufacturer: MuRata; TaMin_C: -55°C; Polarized: N; SizeAreaWB_mm2: 2.08; Value1: Unknown; U/M: EA; Value: 1uF; TaMax_C: 85°C; SizeZ_mm: 0.26; SizeX_mm: 0.6; SizeY_mm: 0.3; Cap_Case: 0201; Value2: 10V; SizeArea_mm2: 0.18; Cap_F: 1µF; AEC Category: Q200
C345 C397 = CMP-0006545-1: CAP, CERM, 22 uF, 6.3 V, +/- 20%, X5R, 0402; Manufacturer: MuRata; TaMin_C: -55°C; Polarized: N; SizeAreaWB_mm2: 3; Value1: Unknown; U/M: EA; Value: 22uF; TaMax_C: 85°C; SizeZ_mm: 0.6; SizeY_mm: 0.5; Cap_Case: 0402; SizeX_mm: 1; Cap_F: 22µF; AEC Category: Q200
C346 C347 C352 = CMP-0009719-2: CAP, CERM, 0.1 uF, 25 V, +/- 10%, X5R, 0201; Manufacturer: MuRata; Polarized: N; Value: 0.1uF; U/M: EA; Cap_F: 100nF; Value1: Unknown; TaMin_C: -55°C; TaMax_C: 85°C; Cap_Case: 0201; SizeArea_mm2: 0.18; SizeAreaWB_mm2: 2.08; SizeX_mm: 0.6; SizeY_mm: 0.3; SizeZ_mm: 0.33; AEC Category: Q200
C348 C349 = CMP-0006620-2: CAP, CERM, 1 uF, 35 V, +/- 20%, X5R, 0402; Manufacturer: MuRata; Polarized: N; Value: 1uF; U/M: EA; Cap_F: 1µF; Value1: Unknown; TaMin_C: -55°C; TaMax_C: 85°C; Cap_Case: 0402; SizeArea_mm2: 0.5; SizeAreaWB_mm2: 3; SizeX_mm: 1; SizeZ_mm: 0.6; AEC Category: Q200
C350 C351 = CMP-0006269-2: CAP, CERM, 4.7 uF, 10 V, +/- 20%, X5R, 0402; Manufacturer: TDK; Polarized: N; Value: 4.7uF; U/M: EA; Cap_F: 4.7µF; Value1: Unknown; TaMin_C: -55°C; TaMax_C: 85°C; Cap_Case: 0402; SizeArea_mm2: 0.5; SizeAreaWB_mm2: 3; SizeX_mm: 1; SizeZ_mm: 0.6; AEC Category: Q200
J19 = CMP-0075593-2: Header, 2.54mm, 4x2, Gold, SMT; Manufacturer: Samtec; Pitch_mm: 2.54; Gender: Male; Shrouded: N; Row_Count: 2; Current_A: 4.9A; Voltage_V: 475V; Cert_CSA: Y; Green_REACh: Passed; Green_Lifecycle: Active
J20-J22 = CMP-0054787-1: Header, 2.54mm, 2x1, Gold, SMT; Manufacturer: Wurth Elektronik; CNHeader: TRUE; Shrouded: N; Gender: Male; Row_Count: 1; Pitch_mm: 2.54; CT: FALSE
J23 = CMP-0055367-1: FFC/FPC Connector, 6 POS, 0.5mm, R/A, Tin, SMT; Manufacturer: Molex; CNHeader: FALSE; Current_A: 5dA; Gender: Female; Voltage_V: 50V; Row_Count: 1; Pitch_mm: 0.5; CT: TRUE; Cert_UL: Y
J24 = CMP-0075405-3: Header, 100mil, 2x1, Gold, TH; Manufacturer: Samtec; Pitch_mm: 2.54; Gender: Male; Shrouded: N; Row_Count: 1; Current_A: 6.3A; Voltage_V: 550V; Cert_CSA: Y; Green_Lifecycle: Active; Green_REACh: Passed
R214 = CMP-0026822-3: RES, 0, 5%, 0.063 W, AEC-Q200 Grade 0, 0402; Manufacturer: Vishay-Dale; Value: 0; Value_Code: 0000; Power_W: 63mW; Value2: 0.063W; VDC_V: 50V; TempCo: 200 ppm/C; SizeArea_mm2: 0.5; SizeX_mm: 1; SizeZ_mm: 0.6; EIA_Code: E24; AEC Category: Q200; AEC Qualified: Y
R215-R220 = CMP-0026823-3: RES, 100 k, 5%, 0.063 W, AEC-Q200 Grade 0, 0402; Manufacturer: Vishay-Dale; Value: 100k; Power_W: 63mW; Value2: 0.063W; VDC_V: 50V; TempCo: 200 ppm/C; SizeArea_mm2: 0.5; SizeX_mm: 1; SizeZ_mm: 0.6; EIA_Code: E24; AEC Category: Q200; AEC Qualified: Y; AEC Grade: 0
S4 = CMP-0002114-3: Switch, SPST 6Pos, SMT; Manufacturer: C&K Components; VDC_V: 24V; SwitchFunction: Off-On; PositionCount: 6; CurrentRating_mA: 25A
TP59 TP61-TP66 = CMP-0055152-1: Test Point, Miniature, SMT; Manufacturer: Keystone; CNHeader: FALSE; Green_Lifecycle: Active; Green_REACh: Passed; CT: TRUE
TP60 = CMP-0055137-1: as TP49 on sheet TPS6508641_Project_Buck12
U16 = CMP-0079627-1: Configurable Multi-Rail PMIC for 2S & 3S Li-Ion Battery-Operated Devices or Non Battery Operated, RSK0064C (VQFN-64); Alternate PartNumber: TPS65086100RSKR; Alternate Manufacturer: Texas Instruments; SizeAreaWB_mm2: 100; SizeZ_mm: 1; SizeX_mm: 8; SizeArea_mm2: 64; CompType: IC; AEC Qualified: N; AEC Category: Q200

## Sheet TPS6508641_Support_Devices.SchDoc
size 431 x 279 mm; Date: Not shown in title block; ApprovedBy: Not shown in title block; CheckedBy: Not shown in title block; Author: Not shown in title block; CompanyName: Not shown in title block; Engineer: Not shown in title block; Organization: Not shown in title block; Address1: Not shown in title block; Address2: Not shown in title block; Address3: Not shown in title block; Address4: Not shown in title block; DocumentNumber: 14; Revision: Use project parameter SCH_Rev; SheetNumber: 14; SheetTotal: 17; PageSetup: Record=PageOptions¦CenterHorizontal=True¦CenterVertical=True¦PrintScale=1.00¦XCorrection=1.00¦YCorrection=1.00¦PrintKind=0¦BorderSize=5000000¦LeftOffset=0¦BottomOffset=0¦Orientation=2¦PaperLength=1000¦PaperWidth=1000¦Scale=100¦PaperSource=15¦PrintQuality=600¦MediaType=1¦DitherType=10¦PaperKind=Letter¦PrintScaleMode=1
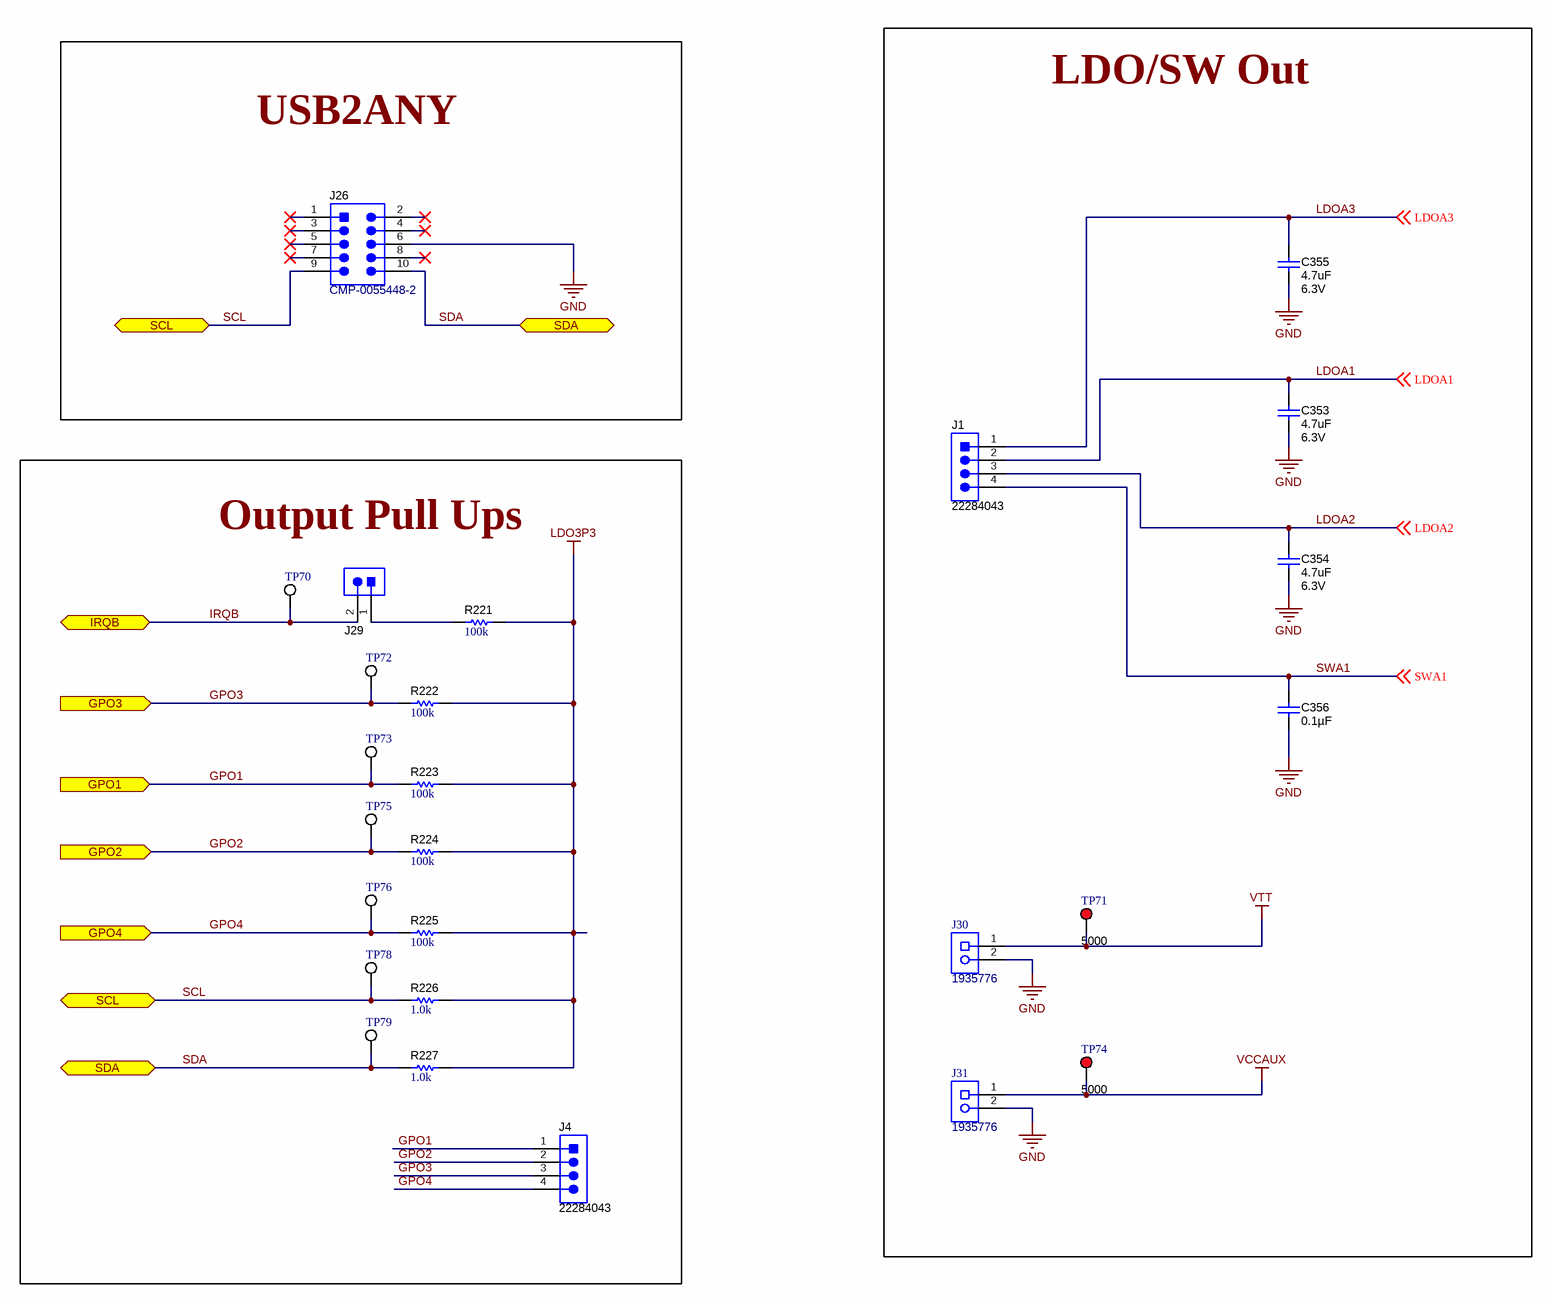
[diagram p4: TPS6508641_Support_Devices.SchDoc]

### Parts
C353  ValueDisplayed: 4.7uF  VDC_V: 6.3V  [0402_065S]  (hidden comment: GRM155R60J475ME87D)
C354  ValueDisplayed: 4.7uF  VDC_V: 6.3V  [0402_065S]  (hidden comment: GRM155R60J475ME87D)
C355  ValueDisplayed: 4.7uF  VDC_V: 6.3V  [0402_065S]  (hidden comment: GRM155R60J475ME87D)
C356  ValueDisplayed: 0.1µF  [0201_033L]  (hidden comment: GRM033R61C104KE14D)
J1  22284043  [Molex_0022284043]
J4  22284043  [Molex_0022284043]
J26  CMP-0055448-2  [CONN_2510-6002]
J29  TSW-102-07-G-S  [TSW-102-07-G-S]  (value not drawn)
J30  1935776  [Phoenix_1935776]
J31  1935776  [Phoenix_1935776]
R221  ValueDisplayed: 100k  [0402S]  (hidden comment: CRCW0402100KJNED)
R222  ValueDisplayed: 100k  [0402S]  (hidden comment: CRCW0402100KJNED)
R223  ValueDisplayed: 100k  [0402S]  (hidden comment: CRCW0402100KJNED)
R224  ValueDisplayed: 100k  [0402S]  (hidden comment: CRCW0402100KJNED)
R225  ValueDisplayed: 100k  [0402S]  (hidden comment: CRCW0402100KJNED)
R226  ValueDisplayed: 1.0k  [0402S]  (hidden comment: CRCW04021K00JNED)
R227  ValueDisplayed: 1.0k  [0402S]  (hidden comment: CRCW04021K00JNED)
TP70  5015  [Testpoint_Keystone_Miniature]  (value not drawn)
TP71  5000  [Keystone5000]
TP72  5015  [Testpoint_Keystone_Miniature]  (value not drawn)
TP73  5015  [Testpoint_Keystone_Miniature]  (value not drawn)
TP74  5000  [Keystone5000]
TP75  5015  [Testpoint_Keystone_Miniature]  (value not drawn)
TP76  5015  [Testpoint_Keystone_Miniature]  (value not drawn)
TP78  5015  [Testpoint_Keystone_Miniature]  (value not drawn)
TP79  5015  [Testpoint_Keystone_Miniature]  (value not drawn)

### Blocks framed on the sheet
USB2ANY: J26
LDO/SW Out: C353-C356 J1 J30 J31 TP71 TP74
Output Pull Ups: J4 J29 R221-R227 TP70 TP72 TP73 TP75 TP76 TP78 TP79

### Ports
GPO1 (in), GPO2 (in), GPO3 (in), GPO4 (in), IRQB (bidir), SCL (bidir), SDA (bidir)

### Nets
GND: C353.2 C354.2 C355.2 C356.2 J26.6 J30.2 J31.2
LDO3P3: R221.1 R222.1 R223.1 R224.1 R225.1 R226.2 R227.2
VCCAUX: J31.1 TP74.1
VTT: J30.1 TP71.1
GPO1: J4.1 R223.2 TP73.1 ; port GPO1
GPO2: J4.2 R224.2 TP75.1 ; port GPO2
GPO3: J4.3 R222.2 TP72.1 ; port GPO3
GPO4: J4.4 R225.2 TP76.1 ; port GPO4
IRQB: J29.2 TP70.1 ; port IRQB
LDOA1: C353.1 J1.2 ; off-sheet LDOA1
LDOA2: C354.1 J1.3 ; off-sheet LDOA2
LDOA3: C355.1 J1.1 ; off-sheet LDOA3
SCL: J26.9 R226.1 TP78.1 ; port SCL
SDA: J26.10 R227.1 TP79.1 ; port SDA
SWA1: C356.1 J1.4 ; off-sheet SWA1
NetJ29_1: J29.1 R221.2

Not connected (* = marked no-connect by the designer): J26 1* 2* 3* 4* 5* 7* 8*

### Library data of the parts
C353-C355 = CMP-0006553-3: CAP, CERM, 4.7 uF, 6.3 V, +/- 20%, X5R, 0402; Manufacturer: MuRata; Polarized: N; Value: 4.7uF; U/M: EA; Cap_F: 4.7µF; ESR_ohm: 9m; Value1: 0.009 ohm; IRMS_A: 1.22A; TaMin_C: -55°C; TaMax_C: 85°C; Cap_Case: 0402; SizeArea_mm2: 0.5; SizeAreaWB_mm2: 3; SizeX_mm: 1; SizeZ_mm: 0.6; AEC Category: Q200; Green_Lifecycle: Active; Green_REACh: Incomplete
C356 = CMP-0086192-1: CAP, CERM, 0.1 µF, 16 V,+/- 10%, X5R, 0201; Manufacturer: MuRata; Value2: 16V; TaMax_C: 85°C; AEC Category: Q200; U/M: EA; SizeZ_mm: 0.33; SizeArea_mm2: 0.18; Polarized: N; SizeAreaWB_mm2: 2.08; Cap_F: 100nF; Cap_Case: 0201; SizeY_mm: 0.3; SizeX_mm: 0.6; Value: 0.1uF; TaMin_C: -55°C
J1 J4 = CMP-0055331-1: Header, 2.54mm, 4x1, Tin, TH; Manufacturer: Molex; CNHeader: TRUE; Current_A: 4A; Shrouded: N; Gender: Male; Voltage_V: 250V; Row_Count: 1; Pitch_mm: 2.54; CT: FALSE; Cert_UL: Y
J26 = CMP-0055448-2: Header (shrouded), 100mil, 5x2, High-Temperature, Gold, TH; PartNumber: N2510-6002-RB; Manufacturer: 3M; Green_Lifecycle: Active; Green_REACh: Passed
J29 = CMP-0075405-3: as J24 on sheet TPS6508641_Project_TPS65086
J30 J31 = CMP-0055506-1: as J14 on sheet TPS6508641_Project_Buck12
R221-R225 = CMP-0026823-3: as R215 on sheet TPS6508641_Project_TPS65086
R226 R227 = CMP-0026852-3: RES, 1.0 k, 5%, 0.063 W, AEC-Q200 Grade 0, 0402; Manufacturer: Vishay-Dale; Value: 1.0k; Res_ohm: 1k; Value_Code: 1k00; Power_W: 63mW; Value2: 0.063W; VDC_V: 50V; TempCo: 200 ppm/C; SizeArea_mm2: 0.5; SizeX_mm: 1; SizeZ_mm: 0.6; EIA_Code: E24; AEC Category: Q200; AEC Qualified: Y; AEC Grade: 0
TP70 TP72 TP73 TP75 TP76 TP78 TP79 = CMP-0055152-1: as TP59 on sheet TPS6508641_Project_TPS65086
TP71 TP74 = CMP-0055137-1: as TP49 on sheet TPS6508641_Project_Buck12

## Sheet TPSM5D1806 IND.SchDoc
size A2; Date: Not shown in title block; ApprovedBy: Not shown in title block; CheckedBy: Not shown in title block; Author: Not shown in title block; CompanyName: Not shown in title block; Engineer: Not shown in title block; Organization: Not shown in title block; Address1: Not shown in title block; Address2: Not shown in title block; Address3: Not shown in title block; Address4: Not shown in title block; DocumentNumber: 15; Revision: Use project parameter SCH_Rev; SheetNumber: 15; SheetTotal: 17; PageSetup: Record=PageOptions¦CenterHorizontal=True¦CenterVertical=True¦PrintScale=1.00¦XCorrection=1.00¦YCorrection=1.00¦PrintKind=0¦BorderSize=5000000¦LeftOffset=0¦BottomOffset=0¦Orientation=2¦PaperLength=1000¦PaperWidth=1000¦Scale=100¦PaperSource=15¦PrintQuality=600¦MediaType=1¦DitherType=10¦PaperKind=Letter¦PrintScaleMode=1
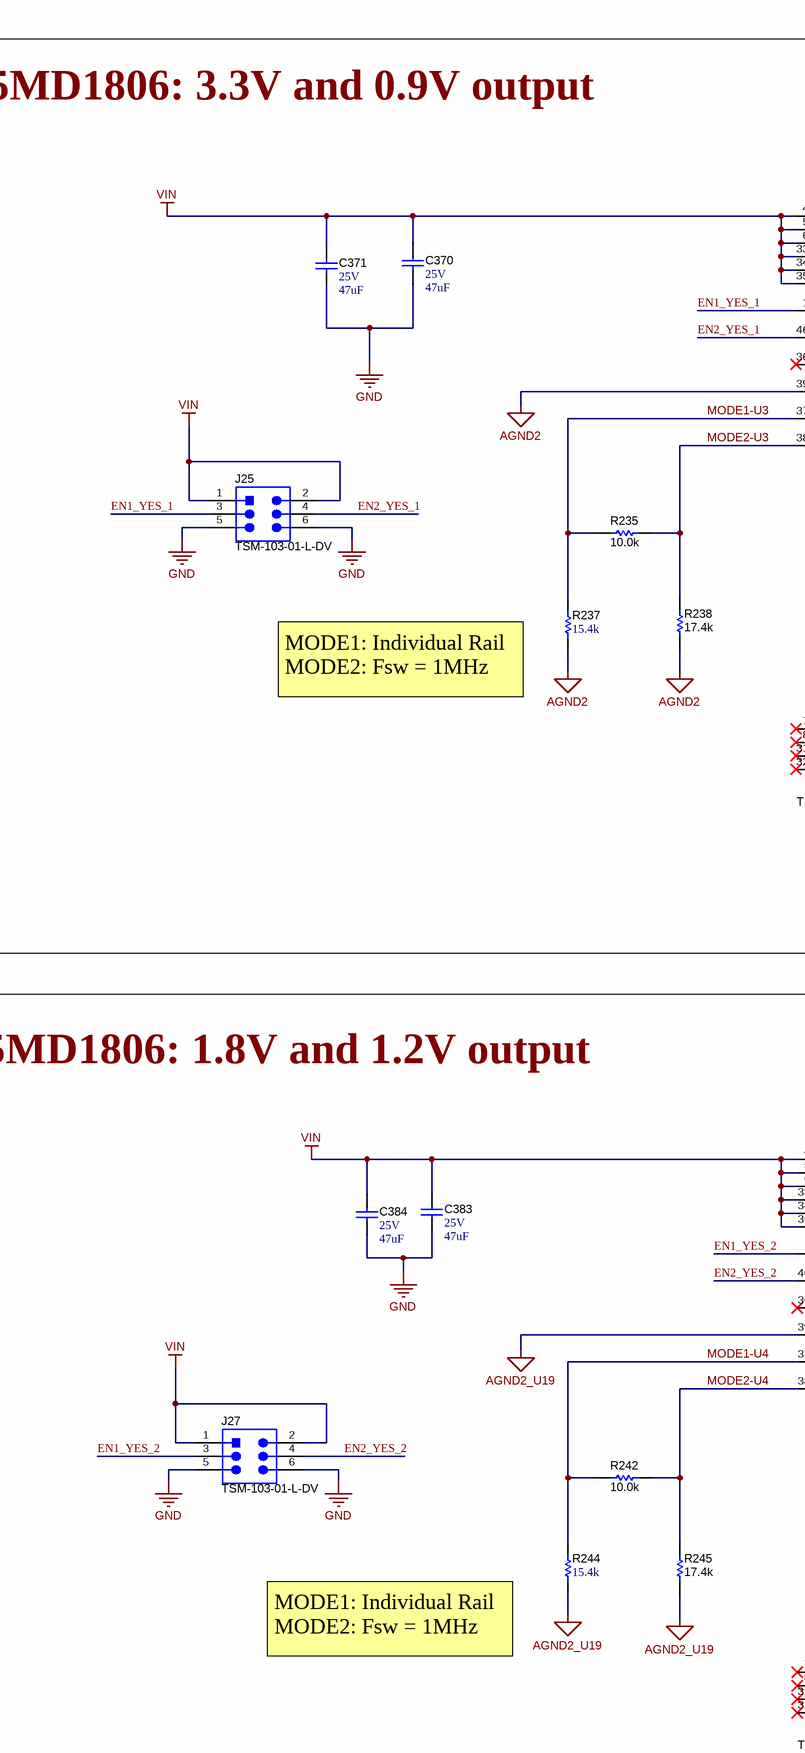
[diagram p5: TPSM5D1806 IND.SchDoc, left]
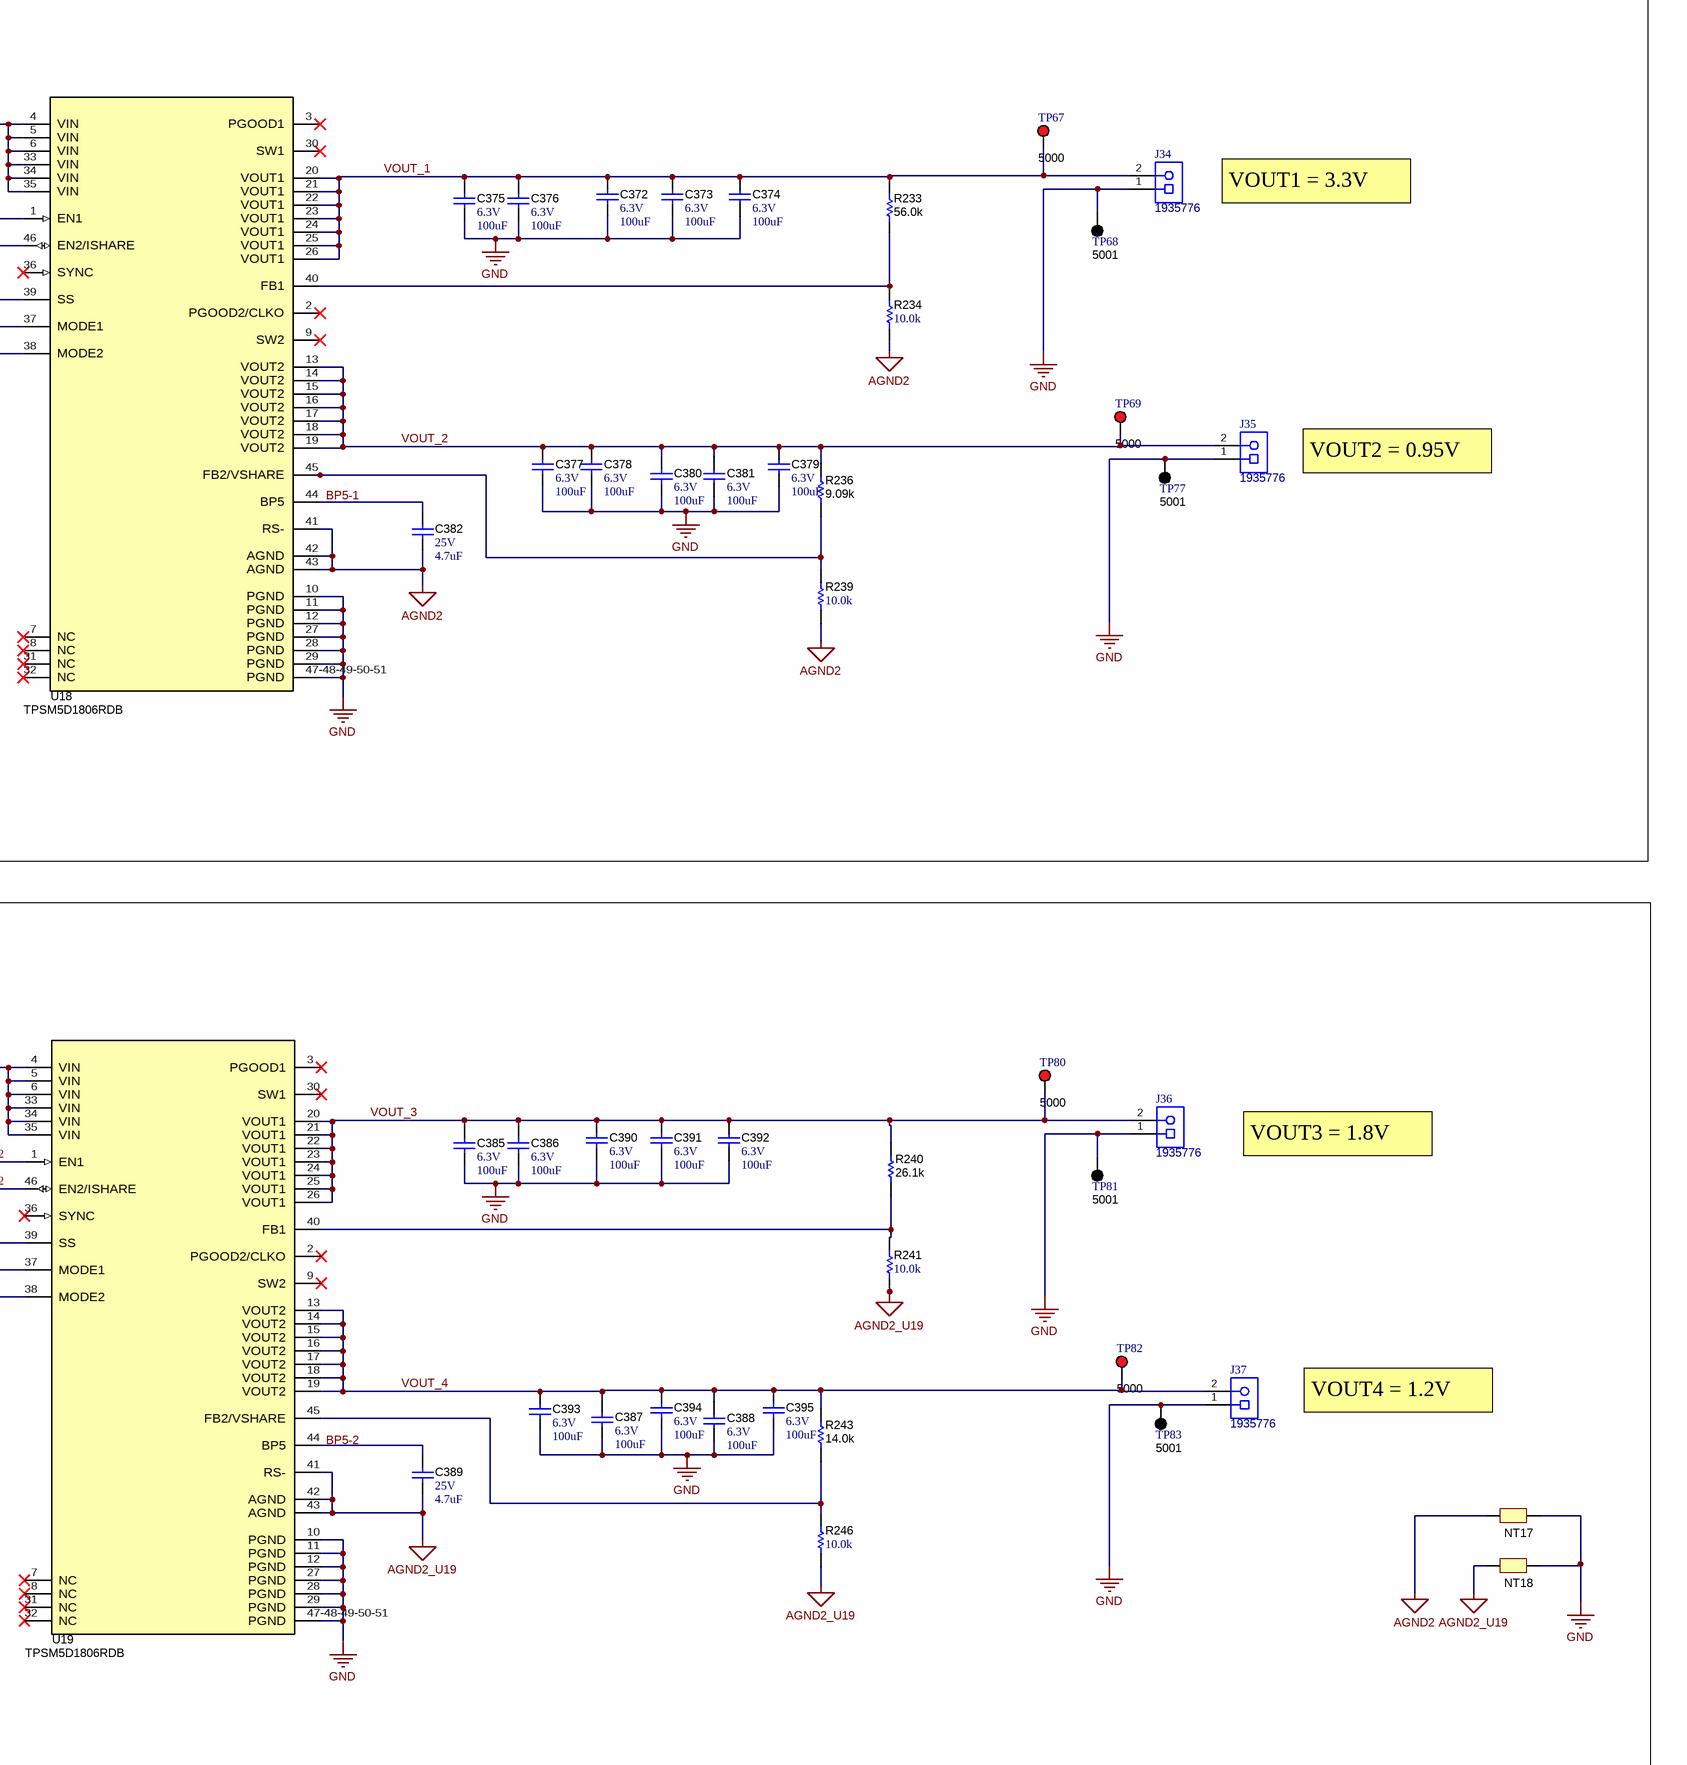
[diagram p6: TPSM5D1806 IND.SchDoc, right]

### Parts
C370  VDC_V: 25V  ValueDisplayed: 47uF  [1206L]  (hidden comment: C3216JB1E476M160AC)
C371  VDC_V: 25V  ValueDisplayed: 47uF  [1206L]  (hidden comment: C3216JB1E476M160AC)
C372  VDC_V: 6.3V  ValueDisplayed: 100uF  [0805L]  (hidden comment: GRM21BR60J107M)
C373  VDC_V: 6.3V  ValueDisplayed: 100uF  [0805L]  (hidden comment: GRM21BR60J107M)
C374  VDC_V: 6.3V  ValueDisplayed: 100uF  [0805L]  (hidden comment: GRM21BR60J107M)
C375  VDC_V: 6.3V  ValueDisplayed: 100uF  [0805L]  (hidden comment: GRM21BR60J107M)
C376  VDC_V: 6.3V  ValueDisplayed: 100uF  [0805L]  (hidden comment: GRM21BR60J107M)
C377  VDC_V: 6.3V  ValueDisplayed: 100uF  [0805L]  (hidden comment: GRM21BR60J107M)
C378  VDC_V: 6.3V  ValueDisplayed: 100uF  [0805L]  (hidden comment: GRM21BR60J107M)
C379  VDC_V: 6.3V  ValueDisplayed: 100uF  [0805L]  (hidden comment: GRM21BR60J107M)
C380  VDC_V: 6.3V  ValueDisplayed: 100uF  [0805L]  (hidden comment: GRM21BR60J107M)
C381  VDC_V: 6.3V  ValueDisplayed: 100uF  [0805L]  (hidden comment: GRM21BR60J107M)
C382  VDC_V: 25V  ValueDisplayed: 4.7uF  [0402S]  (hidden comment: GRM155R61E475ME15)
C383  VDC_V: 25V  ValueDisplayed: 47uF  [1206L]  (hidden comment: C3216JB1E476M160AC)
C384  VDC_V: 25V  ValueDisplayed: 47uF  [1206L]  (hidden comment: C3216JB1E476M160AC)
C385  VDC_V: 6.3V  ValueDisplayed: 100uF  [0805L]  (hidden comment: GRM21BR60J107M)
C386  VDC_V: 6.3V  ValueDisplayed: 100uF  [0805L]  (hidden comment: GRM21BR60J107M)
C387  VDC_V: 6.3V  ValueDisplayed: 100uF  [0805L]  (hidden comment: GRM21BR60J107M)
C388  VDC_V: 6.3V  ValueDisplayed: 100uF  [0805L]  (hidden comment: GRM21BR60J107M)
C389  VDC_V: 25V  ValueDisplayed: 4.7uF  [0402S]  (hidden comment: GRM155R61E475ME15)
C390  VDC_V: 6.3V  ValueDisplayed: 100uF  [0805L]  (hidden comment: GRM21BR60J107M)
C391  VDC_V: 6.3V  ValueDisplayed: 100uF  [0805L]  (hidden comment: GRM21BR60J107M)
C392  VDC_V: 6.3V  ValueDisplayed: 100uF  [0805L]  (hidden comment: GRM21BR60J107M)
C393  VDC_V: 6.3V  ValueDisplayed: 100uF  [0805L]  (hidden comment: GRM21BR60J107M)
C394  VDC_V: 6.3V  ValueDisplayed: 100uF  [0805L]  (hidden comment: GRM21BR60J107M)
C395  VDC_V: 6.3V  ValueDisplayed: 100uF  [0805L]  (hidden comment: GRM21BR60J107M)
J25  TSM-103-01-L-DV  [Samtec_TSM-103-01-x-DV]
J27  TSM-103-01-L-DV  [Samtec_TSM-103-01-x-DV]
J34  1935776  [Phoenix_1935776]
J35  1935776  [Phoenix_1935776]
J36  1935776  [Phoenix_1935776]
J37  1935776  [Phoenix_1935776]
NT17  Net-Tie  [Net-Tie_10mil]  (value not drawn)  (net tie, no BOM)
NT18  Net-Tie  [Net-Tie_10mil]  (value not drawn)  (net tie, no BOM)
R233  ValueDisplayed: 56.0k  [0201L]  (hidden comment: CRCW020156K0FKED)
R234  ValueDisplayed: 10.0k  [0201L]  (hidden comment: CRCW020110K0FKED)
R235  ValueDisplayed: 10.0k  [0201L]  (hidden comment: RC0201FR-7D10KL)
R236  ValueDisplayed: 9.09k  [0201L]  (hidden comment: CRCW02019K09FKED)
R237  ValueDisplayed: 15.4k  [0201L]  (hidden comment: RC0201FR-0715K4L)
R238  ValueDisplayed: 17.4k  [0201L]  (hidden comment: RC0201FR-0717K4L)
R239  ValueDisplayed: 10.0k  [0201L]  (hidden comment: CRCW020110K0FKED)
R240  ValueDisplayed: 26.1k  [0201L]  (hidden comment: RC0201FR-0726K1L)
R241  ValueDisplayed: 10.0k  [0201L]  (hidden comment: CRCW020110K0FKED)
R242  ValueDisplayed: 10.0k  [0201L]  (hidden comment: RC0201FR-7D10KL)
R243  ValueDisplayed: 14.0k  [0201L]  (hidden comment: RC0201FR-0714KL)
R244  ValueDisplayed: 15.4k  [0201L]  (hidden comment: RC0201FR-0715K4L)
R245  ValueDisplayed: 17.4k  [0201L]  (hidden comment: RC0201FR-0717K4L)
R246  ValueDisplayed: 10.0k  [0201L]  (hidden comment: CRCW020110K0FKED)
TP67  5000  [Keystone5000]
TP68  5001  [Keystone5001]
TP69  5000  [Keystone5000]
TP77  5001  [Keystone5001]
TP80  5000  [Keystone5000]
TP81  5001  [Keystone5001]
TP82  5000  [Keystone5000]
TP83  5001  [Keystone5001]
U18  TPSM5D1806RDB  [RDB0051A-MFG]
U19  TPSM5D1806RDB  [RDB0051A-MFG]

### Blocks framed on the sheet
TPS5MD1806: 3.3V and 0.9V output: C370-C382 J25 J34 J35 R233-R239 TP67-TP69 TP77 U18
TPS5MD1806: 1.8V and 1.2V output: C383-C395 J27 J36 J37 NT17 NT18 R240-R246 TP80-TP83 U19

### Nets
AGND2: C382.2 NT17.1 R234.2 R237.2 R238.2 R239.1 U18.39(SS) U18.41(RS-) U18.42(AGND) U18.43(AGND)
AGND2_U19: C389.2 NT18.1 R241.2 R244.2 R245.2 R246.1 U19.39(SS) U19.41(RS-) U19.42(AGND) U19.43(AGND)
GND: C370.2 C371.2 C372.2 C373.2 C374.2 C375.2 C376.2 C377.2 C378.2 C379.2 C380.2 C381.2 C383.2 C384.2 C385.2 C386.2 C387.2 C388.2 C390.2 C391.2 C392.2 C393.2 C394.2 C395.2 J25.5 J25.6 J27.5 J27.6 J34.1 J35.1 J36.1 J37.1 NT17.2 NT18.2 TP68.1 TP77.1 TP81.1 TP83.1 U18.10(PGND) U18.11(PGND) U18.12(PGND) U18.27(PGND) U18.28(PGND) U18.29(PGND) U18.47-48-49-50-51(PGND) U19.10(PGND) U19.11(PGND) U19.12(PGND) U19.27(PGND) U19.28(PGND) U19.29(PGND) U19.47-48-49-50-51(PGND)
VIN: C370.1 C371.1 C383.1 C384.1 J25.1 J25.2 J27.1 J27.2 U18.4(VIN) U18.5(VIN) U18.6(VIN) U18.33(VIN) U18.34(VIN) U18.35(VIN) U19.4(VIN) U19.5(VIN) U19.6(VIN) U19.33(VIN) U19.34(VIN) U19.35(VIN)
EN1_YES_1: J25.3 U18.1(EN1)
EN1_YES_2: J27.3 U19.1(EN1)
EN2_YES_1: J25.4 U18.46(EN2/ISHARE)
EN2_YES_2: J27.4 U19.46(EN2/ISHARE)
MODE1-U3: R235.2 R237.1 U18.37(MODE1)
MODE1-U4: R242.2 R244.1 U19.37(MODE1)
MODE2-U3: R235.1 R238.1 U18.38(MODE2)
MODE2-U4: R242.1 R245.1 U19.38(MODE2)
VOUT_1: C372.1 C373.1 C374.1 C375.1 C376.1 J34.2 R233.2 TP67.1 U18.20(VOUT1) U18.21(VOUT1) U18.22(VOUT1) U18.23(VOUT1) U18.24(VOUT1) U18.25(VOUT1) U18.26(VOUT1)
VOUT_2: C377.1 C378.1 C379.1 C380.1 C381.1 J35.2 R236.2 TP69.1 U18.13(VOUT2) U18.14(VOUT2) U18.15(VOUT2) U18.16(VOUT2) U18.17(VOUT2) U18.18(VOUT2) U18.19(VOUT2)
VOUT_3: C385.1 C386.1 C390.1 C391.1 C392.1 J36.2 R240.2 TP80.1 U19.20(VOUT1) U19.21(VOUT1) U19.22(VOUT1) U19.23(VOUT1) U19.24(VOUT1) U19.25(VOUT1) U19.26(VOUT1)
VOUT_4: C387.1 C388.1 C393.1 C394.1 C395.1 J37.2 R243.2 TP82.1 U19.13(VOUT2) U19.14(VOUT2) U19.15(VOUT2) U19.16(VOUT2) U19.17(VOUT2) U19.18(VOUT2) U19.19(VOUT2)
NetC382_1: C382.1 U18.44(BP5)
NetC389_1: C389.1 U19.44(BP5)
NetR233_1: R233.1 R234.1 U18.40(FB1)
NetR236_1: R236.1 R239.2 U18.45(FB2/VSHARE)
NetR240_1: R240.1 R241.1 U19.40(FB1)
NetR243_1: R243.1 R246.2 U19.45(FB2/VSHARE)

Not connected (* = marked no-connect by the designer): U18 2(PGOOD2/CLKO)* 3(PGOOD1)* 7(NC)* 8(NC)* 9(SW2)* 30(SW1)* 31(NC)* 32(NC)* 36(SYNC)*; U19 2(PGOOD2/CLKO)* 3(PGOOD1)* 7(NC)* 8(NC)* 9(SW2)* 30(SW1)* 31(NC)* 32(NC)* 36(SYNC)*

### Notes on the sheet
- VOUT1 = 3.3V
- VOUT2 = 0.95V
- (near R237) MODE1: Individual Rail
  MODE2: Fsw = 1MHz
- VOUT3 = 1.8V
- VOUT4 = 1.2V
- MODE1: Individual Rail
  MODE2: Fsw = 1MHz
- Labels drawn without touching a wire or pin: BP5-1, BP5-2

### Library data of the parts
C370 C371 C383 C384 = CMP-0008646-2: CAP, CERM, 47 uF, 25 V, +/- 20%, JB, 1206; Manufacturer: TDK; TaMin_C: -55°C; Polarized: N; SizeAreaWB_mm2: 10.92; Value1: Unknown; U/M: EA; Value: 47uF; TaMax_C: 85°C; SizeZ_mm: 1.35; SizeX_mm: 3.2; SizeY_mm: 1.6; Cap_Case: 1206; SizeArea_mm2: 5.12; Cap_F: 47µF; AEC Category: Q200
C372-C381 C385-C388 C390-C395 = CMP-0008280-2: as C309 on sheet TPS6508641_Project_Buck12
C382 C389 = CMP-0006612-2: CAP, CERM, 4.7 uF, 25 V, +/- 20%, X5R, 0402; Manufacturer: MuRata; TaMin_C: -55°C; Polarized: N; SizeAreaWB_mm2: 3; Value1: Unknown; U/M: EA; Value: 4.7uF; TaMax_C: 85°C; SizeZ_mm: 0.6; SizeX_mm: 1; SizeY_mm: 0.5; Cap_Case: 0402; Cap_F: 4.7µF; AEC Category: Q200
J25 J27 = CMP-0075648-2: Header, 2.54mm, 3x2, Gold, SMT; Manufacturer: Samtec; Pitch_mm: 2.54; Gender: Male; Cert_CSA: Y; Green_REACh: Passed; Current_A: 4.9A; Voltage_V: 475V; Shrouded: N; Green_Lifecycle: Active; Row_Count: 2
J34-J37 = CMP-0055506-1: as J14 on sheet TPS6508641_Project_Buck12
NT17 NT18 = CMP-0078142-4: Single point connection between nets.
R233 = CMP-0027281-3: RES, 56.0 k, 1%, 0.05 W, 0201; Manufacturer: Vishay-Dale; Power_W: 50mW; TempCo: 100 ppm/C; Value_Code: 56k0; Value: 56.0k; Res_ohm: 56k; SizeX_mm: 0.6; SizeY_mm: 0.3; SizeZ_mm: 0.26; Value2: 0.05W; SizeArea_mm2: 0.18; AEC Qualified: N; VDC_V: 30V; AEC Category: Q200
R234 R239 R241 R246 = CMP-0027262-3: RES, 10.0 k, 1%, 0.05 W, 0201; Manufacturer: Vishay-Dale; Power_W: 50mW; TempCo: 100 ppm/C; Value_Code: 10k0; Value: 10.0k; EIA_Code: E96; Res_ohm: 10k; SizeX_mm: 0.6; SizeY_mm: 0.3; SizeZ_mm: 0.26; Value2: 0.05W; SizeArea_mm2: 0.18; AEC Qualified: N; VDC_V: 30V; AEC Category: Q200
R235 R242 = CMP-0027945-1: RES, 10.0 k, 1%, 0.05 W, 0201; Manufacturer: Yageo America; Power_W: 50mW; TempCo: 200 ppm/C; Value_Code: 10k0; U/M: EA; Value: 10.0k; EIA_Code: E96; Res_ohm: 10k; SizeX_mm: 0.6; SizeY_mm: 0.3; SizeZ_mm: 0.26; Value2: 0.05W; SizeArea_mm2: 0.18; AEC Qualified: N; VDC_V: 25V; AEC Category: Q200
R236 = CMP-0027284-3: RES, 9.09 k, 1%, 0.05 W, 0201; Manufacturer: Vishay-Dale; Power_W: 50mW; TempCo: 100 ppm/C; Value_Code: 9k09; Value: 9.09k; EIA_Code: E96; SizeX_mm: 0.6; SizeY_mm: 0.3; SizeZ_mm: 0.26; Value2: 0.05W; SizeArea_mm2: 0.18; AEC Qualified: N; VDC_V: 30V; AEC Category: Q200
R237 R244 = CMP-0027372-2: RES, 15.4 k, 1%, 0.05 W, 0201; Manufacturer: Yageo America; Power_W: 50mW; TempCo: 200 ppm/C; Value_Code: 15k4; U/M: EA; Value: 15.4k; EIA_Code: E96; SizeX_mm: 0.6; SizeY_mm: 0.3; SizeZ_mm: 0.26; Value2: 0.05W; SizeArea_mm2: 0.18; AEC Qualified: N; VDC_V: 25V; AEC Category: Q200
R238 R245 = CMP-0027398-2: RES, 17.4 k, 1%, 0.05 W, 0201; Manufacturer: Yageo America; Power_W: 50mW; TempCo: 200 ppm/C; Value_Code: 17k4; U/M: EA; Value: 17.4k; EIA_Code: E96; SizeX_mm: 0.6; SizeY_mm: 0.3; SizeZ_mm: 0.26; Value2: 0.05W; SizeArea_mm2: 0.18; AEC Qualified: N; VDC_V: 25V; AEC Category: Q200
R240 = CMP-0027529-1: RES, 26.1 k, 1%, 0.05 W, 0201; Manufacturer: Yageo America; Power_W: 50mW; TempCo: 200 ppm/C; Value_Code: 26k1; U/M: EA; Value: 26.1k; EIA_Code: E96; SizeX_mm: 0.6; SizeY_mm: 0.3; SizeZ_mm: 0.26; Value2: 0.05W; SizeArea_mm2: 0.18; AEC Qualified: N; VDC_V: 25V; AEC Category: Q200
R243 = CMP-0027362-2: RES, 14.0 k, 1%, 0.05 W, 0201; Manufacturer: Yageo America; Power_W: 50mW; TempCo: 200 ppm/C; Value_Code: 14k0; U/M: EA; Value: 14.0k; EIA_Code: E96; Res_ohm: 14k; SizeX_mm: 0.6; SizeY_mm: 0.3; SizeZ_mm: 0.26; Value2: 0.05W; SizeArea_mm2: 0.18; AEC Qualified: N; VDC_V: 25V; AEC Category: Q200
TP67 TP69 TP80 TP82 = CMP-0055137-1: as TP49 on sheet TPS6508641_Project_Buck12
TP68 TP77 TP81 TP83 = CMP-0055138-1: as TP50 on sheet TPS6508641_Project_Buck12
U18 U19 = CMP-0088389-1: 4.5-V to 18-V Input, Dual 6-A Output Power Module with Current Sharing; Manufacturer: Texas Instruments; AEC Qualified: No; Switching Frequency: 500/1000/1500/2250kHz; Max Duty Cycle: 80%; Output Voltage: 0.5-5.5V; Output Type: AdjustableProgrammable; TJmax_C: +150°C; Min Supply Voltage: 4.5V; Max Supply Voltage: 18V; Standoff Height: 0mm; Number Of Outputs: 2; Nominal Supply Current: 2500uA; SizeZ_mm: 1.9mm; Switching Topology: Buck; TaMin_C: -40°C; TaMax_C: +105°C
